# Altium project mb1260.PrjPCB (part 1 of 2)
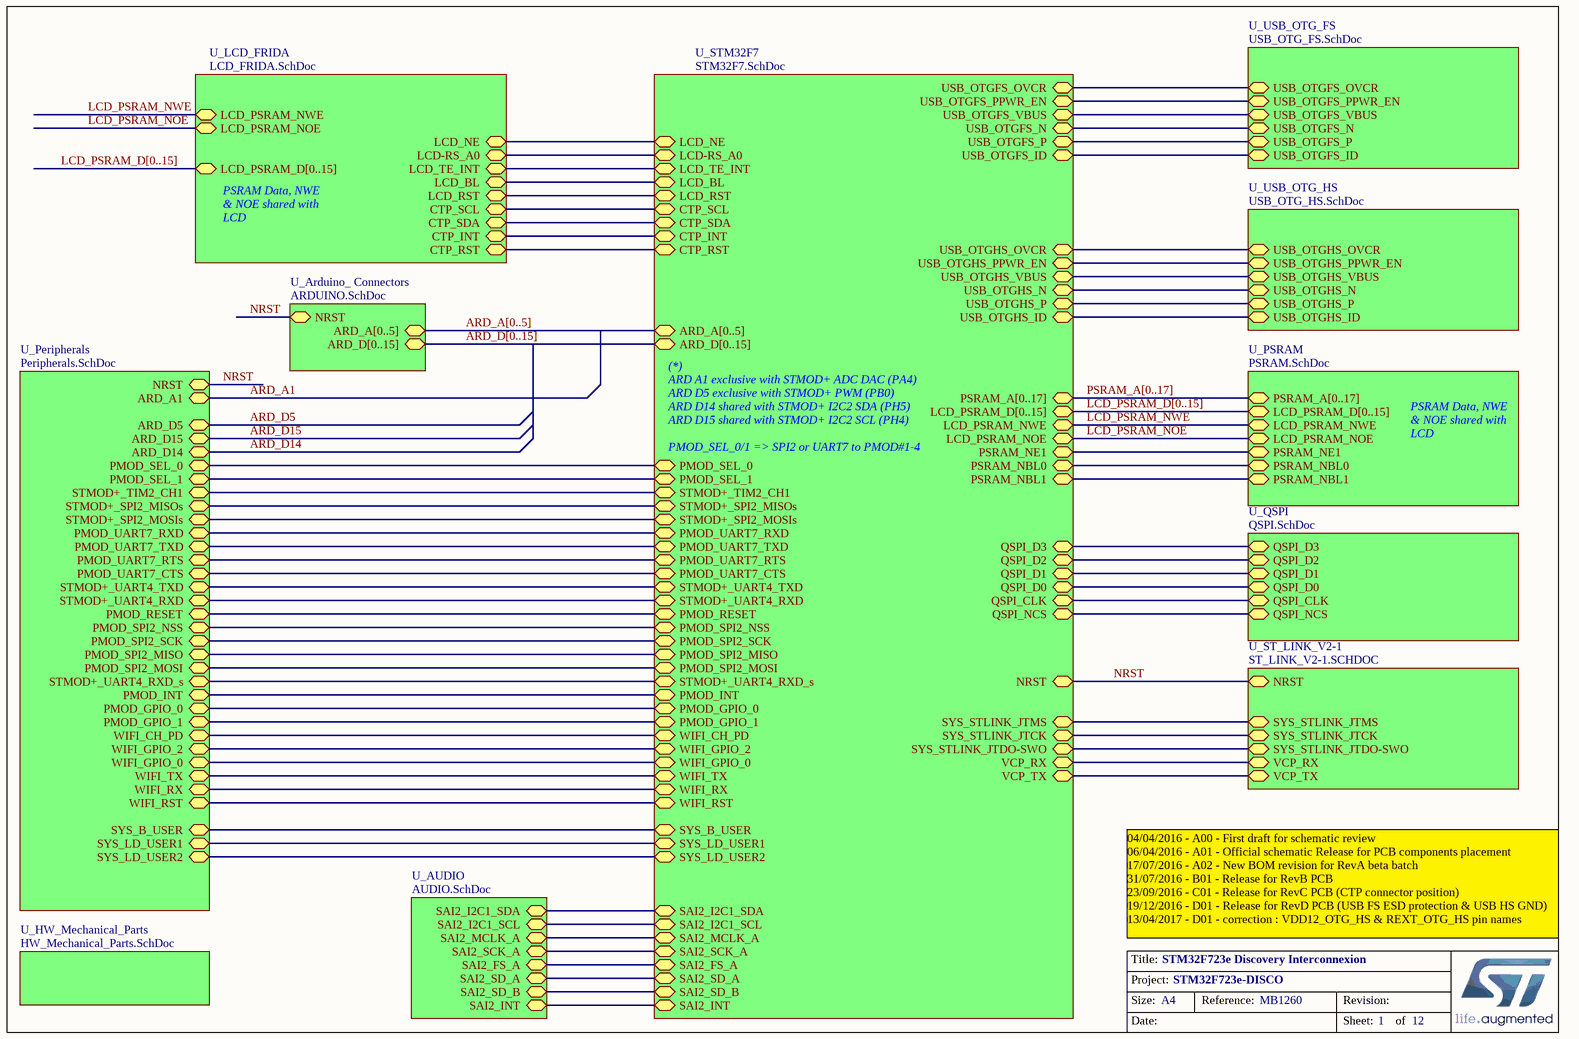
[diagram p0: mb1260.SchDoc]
BOMRevision: D-01; PCBRevision: D-01
12 sheets, 321 parts. Net scope: hierarchical (ports join the sheet entries above them; power ports are global).
Sheets:
  mb1260.SchDoc
    U_ST_LINK_V2-1 = ST_LINK_V2-1.SCHDOC
    U_AUDIO = AUDIO.SchDoc
    U_Peripherals = Peripherals.SchDoc
    U_Arduino_ Connectors = ARDUINO.SchDoc
    U_PSRAM = PSRAM.SchDoc
    U_USB_OTG_FS = USB_OTG_FS.SchDoc
    U_STM32F7 = STM32F7.SchDoc
    U_LCD_FRIDA = LCD_FRIDA.SchDoc
    U_USB_OTG_HS = USB_OTG_HS.SchDoc
    U_QSPI = QSPI.SchDoc
    U_HW_Mechanical_Parts = HW_Mechanical_Parts.SchDoc

## Sheet mb1260.SchDoc: STM32F723e Discovery Interconnexion
size A4; Author: N.P; CompanyName: STMicroelectronics; Organization: MCD/APPLIS/LMS; DocumentNumber: MB1260; Revision: D-01; SheetNumber: 1; SheetTotal: 12; Project: STM32F723e-DISCO; BOM Version: D-01

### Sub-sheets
U_Arduino_ Connectors = ARDUINO.SchDoc: NRST, ARD_D[0..15], ARD_A[0..5]
U_AUDIO = AUDIO.SchDoc: SAI2_I2C1_SDA, SAI2_I2C1_SCL, SAI2_MCLK_A, SAI2_SCK_A, SAI2_FS_A, SAI2_SD_A, SAI2_SD_B, SAI2_INT
U_HW_Mechanical_Parts = HW_Mechanical_Parts.SchDoc: no entries
U_LCD_FRIDA = LCD_FRIDA.SchDoc: LCD_NE, LCD_TE_INT, LCD_BL, LCD_RST, CTP_SCL, CTP_SDA, CTP_INT, CTP_RST, LCD_PSRAM_D[0..15], LCD_PSRAM_NWE, LCD_PSRAM_NOE, LCD-RS_A0
U_Peripherals = Peripherals.SchDoc: NRST, WIFI_TX, WIFI_RX, WIFI_RST, STMOD+_TIM2_CH1, STMOD+_SPI2_MOSIs, PMOD_UART7_RXD, PMOD_UART7_TXD, PMOD_UART7_CTS, PMOD_UART7_RTS, STMOD+_UART4_TXD, STMOD+_UART4_RXD, PMOD_RESET, PMOD_SPI2_SCK, PMOD_SPI2_NSS, PMOD_SPI2_MISO, PMOD_SPI2_MOSI, STMOD+_UART4_RXD_s, PMOD_INT, SYS_B_USER, SYS_LD_USER1, SYS_LD_USER2, ARD_D15, ARD_D14, ARD_A1, ARD_D5, PMOD_GPIO_1, PMOD_GPIO_0, WIFI_GPIO_0, WIFI_GPIO_2, WIFI_CH_PD, PMOD_SEL_1, STMOD+_SPI2_MISOs, PMOD_SEL_0
U_PSRAM = PSRAM.SchDoc: PSRAM_A[0..17], LCD_PSRAM_D[0..15], LCD_PSRAM_NWE, PSRAM_NE1, PSRAM_NBL0, PSRAM_NBL1, LCD_PSRAM_NOE
U_QSPI = QSPI.SchDoc: QSPI_D0, QSPI_D3, QSPI_D1, QSPI_CLK, QSPI_NCS, QSPI_D2
U_ST_LINK_V2-1 = ST_LINK_V2-1.SCHDOC: SYS_STLINK_JTMS, SYS_STLINK_JTCK, SYS_STLINK_JTDO-SWO, VCP_RX, VCP_TX, NRST
U_STM32F7 = STM32F7.SchDoc: QSPI_D0, QSPI_D3, QSPI_D1, QSPI_CLK, QSPI_NCS, SAI2_I2C1_SDA, SAI2_I2C1_SCL, SAI2_MCLK_A, CTP_SCL, CTP_SDA, PSRAM_A[0..17], LCD_PSRAM_D[0..15], LCD_PSRAM_NWE, PSRAM_NE1, PSRAM_NBL0, PSRAM_NBL1, QSPI_D2, ARD_D[0..15], SAI2_SCK_A, SAI2_FS_A, SAI2_SD_A, SAI2_SD_B, SAI2_INT, LCD_NE, LCD_TE_INT, LCD_BL, LCD_RST, CTP_INT, CTP_RST, WIFI_RST, WIFI_RX, WIFI_TX, ARD_A[0..5], LCD_PSRAM_NOE, SYS_STLINK_JTMS, SYS_STLINK_JTCK, SYS_STLINK_JTDO-SWO, VCP_RX, VCP_TX, USB_OTGHS_OVCR, USB_OTGHS_PPWR_EN, USB_OTGHS_VBUS, USB_OTGHS_N, USB_OTGHS_ID, USB_OTGHS_P, USB_OTGFS_OVCR, USB_OTGFS_PPWR_EN, USB_OTGFS_VBUS, USB_OTGFS_P, USB_OTGFS_N, USB_OTGFS_ID, STMOD+_TIM2_CH1, STMOD+_SPI2_MOSIs, PMOD_UART7_RXD, PMOD_UART7_TXD, PMOD_UART7_CTS, PMOD_UART7_RTS, STMOD+_UART4_TXD, STMOD+_UART4_RXD, PMOD_RESET, PMOD_SPI2_SCK, PMOD_SPI2_NSS, PMOD_SPI2_MISO, PMOD_SPI2_MOSI, STMOD+_UART4_RXD_s, PMOD_INT, NRST, SYS_B_USER, SYS_LD_USER1, SYS_LD_USER2, PMOD_GPIO_0, PMOD_GPIO_1, WIFI_GPIO_0, WIFI_GPIO_2, WIFI_CH_PD, LCD-RS_A0, PMOD_SEL_1, STMOD+_SPI2_MISOs, PMOD_SEL_0
U_USB_OTG_FS = USB_OTG_FS.SchDoc: USB_OTGFS_OVCR, USB_OTGFS_PPWR_EN, USB_OTGFS_VBUS, USB_OTGFS_P, USB_OTGFS_N, USB_OTGFS_ID
U_USB_OTG_HS = USB_OTG_HS.SchDoc: USB_OTGHS_OVCR, USB_OTGHS_PPWR_EN, USB_OTGHS_VBUS, USB_OTGHS_N, USB_OTGHS_ID, USB_OTGHS_P

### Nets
CTP_INT: sheet U_STM32F7/CTP_INT, sheet U_LCD_FRIDA/CTP_INT
CTP_RST: sheet U_STM32F7/CTP_RST, sheet U_LCD_FRIDA/CTP_RST
CTP_SCL: sheet U_STM32F7/CTP_SCL, sheet U_LCD_FRIDA/CTP_SCL
CTP_SDA: sheet U_STM32F7/CTP_SDA, sheet U_LCD_FRIDA/CTP_SDA
LCD-RS_A0: sheet U_STM32F7/LCD-RS_A0, sheet U_LCD_FRIDA/LCD-RS_A0
LCD_BL: sheet U_STM32F7/LCD_BL, sheet U_LCD_FRIDA/LCD_BL
LCD_NE: sheet U_STM32F7/LCD_NE, sheet U_LCD_FRIDA/LCD_NE
LCD_PSRAM_NOE: sheet U_PSRAM/LCD_PSRAM_NOE, sheet U_STM32F7/LCD_PSRAM_NOE, sheet U_LCD_FRIDA/LCD_PSRAM_NOE
LCD_PSRAM_NWE: sheet U_PSRAM/LCD_PSRAM_NWE, sheet U_STM32F7/LCD_PSRAM_NWE, sheet U_LCD_FRIDA/LCD_PSRAM_NWE
LCD_RST: sheet U_STM32F7/LCD_RST, sheet U_LCD_FRIDA/LCD_RST
LCD_TE_INT: sheet U_STM32F7/LCD_TE_INT, sheet U_LCD_FRIDA/LCD_TE_INT
NRST: sheet U_ST_LINK_V2-1/NRST, sheet U_Peripherals/NRST, sheet U_Arduino_ Connectors/NRST, sheet U_STM32F7/NRST
PMOD_GPIO_0: sheet U_Peripherals/PMOD_GPIO_0, sheet U_STM32F7/PMOD_GPIO_0
PMOD_GPIO_1: sheet U_Peripherals/PMOD_GPIO_1, sheet U_STM32F7/PMOD_GPIO_1
PMOD_INT: sheet U_Peripherals/PMOD_INT, sheet U_STM32F7/PMOD_INT
PMOD_RESET: sheet U_Peripherals/PMOD_RESET, sheet U_STM32F7/PMOD_RESET
PMOD_SEL_0: sheet U_Peripherals/PMOD_SEL_0, sheet U_STM32F7/PMOD_SEL_0
PMOD_SEL_1: sheet U_Peripherals/PMOD_SEL_1, sheet U_STM32F7/PMOD_SEL_1
PMOD_SPI2_MISO: sheet U_Peripherals/PMOD_SPI2_MISO, sheet U_STM32F7/PMOD_SPI2_MISO
PMOD_SPI2_MOSI: sheet U_Peripherals/PMOD_SPI2_MOSI, sheet U_STM32F7/PMOD_SPI2_MOSI
PMOD_SPI2_NSS: sheet U_Peripherals/PMOD_SPI2_NSS, sheet U_STM32F7/PMOD_SPI2_NSS
PMOD_SPI2_SCK: sheet U_Peripherals/PMOD_SPI2_SCK, sheet U_STM32F7/PMOD_SPI2_SCK
PMOD_UART7_CTS: sheet U_Peripherals/PMOD_UART7_CTS, sheet U_STM32F7/PMOD_UART7_CTS
PMOD_UART7_RTS: sheet U_Peripherals/PMOD_UART7_RTS, sheet U_STM32F7/PMOD_UART7_RTS
PMOD_UART7_RXD: sheet U_Peripherals/PMOD_UART7_RXD, sheet U_STM32F7/PMOD_UART7_RXD
PMOD_UART7_TXD: sheet U_Peripherals/PMOD_UART7_TXD, sheet U_STM32F7/PMOD_UART7_TXD
PSRAM_NBL0: sheet U_PSRAM/PSRAM_NBL0, sheet U_STM32F7/PSRAM_NBL0
PSRAM_NBL1: sheet U_PSRAM/PSRAM_NBL1, sheet U_STM32F7/PSRAM_NBL1
PSRAM_NE1: sheet U_PSRAM/PSRAM_NE1, sheet U_STM32F7/PSRAM_NE1
QSPI_CLK: sheet U_STM32F7/QSPI_CLK, sheet U_QSPI/QSPI_CLK
QSPI_D0: sheet U_STM32F7/QSPI_D0, sheet U_QSPI/QSPI_D0
QSPI_D1: sheet U_STM32F7/QSPI_D1, sheet U_QSPI/QSPI_D1
QSPI_D2: sheet U_STM32F7/QSPI_D2, sheet U_QSPI/QSPI_D2
QSPI_D3: sheet U_STM32F7/QSPI_D3, sheet U_QSPI/QSPI_D3
QSPI_NCS: sheet U_STM32F7/QSPI_NCS, sheet U_QSPI/QSPI_NCS
SAI2_FS_A: sheet U_AUDIO/SAI2_FS_A, sheet U_STM32F7/SAI2_FS_A
SAI2_I2C1_SCL: sheet U_AUDIO/SAI2_I2C1_SCL, sheet U_STM32F7/SAI2_I2C1_SCL
SAI2_I2C1_SDA: sheet U_AUDIO/SAI2_I2C1_SDA, sheet U_STM32F7/SAI2_I2C1_SDA
SAI2_INT: sheet U_AUDIO/SAI2_INT, sheet U_STM32F7/SAI2_INT
SAI2_MCLK_A: sheet U_AUDIO/SAI2_MCLK_A, sheet U_STM32F7/SAI2_MCLK_A
SAI2_SCK_A: sheet U_AUDIO/SAI2_SCK_A, sheet U_STM32F7/SAI2_SCK_A
SAI2_SD_A: sheet U_AUDIO/SAI2_SD_A, sheet U_STM32F7/SAI2_SD_A
SAI2_SD_B: sheet U_AUDIO/SAI2_SD_B, sheet U_STM32F7/SAI2_SD_B
STMOD+_SPI2_MISOs: sheet U_Peripherals/STMOD+_SPI2_MISOs, sheet U_STM32F7/STMOD+_SPI2_MISOs
STMOD+_SPI2_MOSIs: sheet U_Peripherals/STMOD+_SPI2_MOSIs, sheet U_STM32F7/STMOD+_SPI2_MOSIs
STMOD+_TIM2_CH1: sheet U_Peripherals/STMOD+_TIM2_CH1, sheet U_STM32F7/STMOD+_TIM2_CH1
STMOD+_UART4_RXD: sheet U_Peripherals/STMOD+_UART4_RXD, sheet U_STM32F7/STMOD+_UART4_RXD
STMOD+_UART4_RXD_s: sheet U_Peripherals/STMOD+_UART4_RXD_s, sheet U_STM32F7/STMOD+_UART4_RXD_s
STMOD+_UART4_TXD: sheet U_Peripherals/STMOD+_UART4_TXD, sheet U_STM32F7/STMOD+_UART4_TXD
SYS_B_USER: sheet U_Peripherals/SYS_B_USER, sheet U_STM32F7/SYS_B_USER
SYS_LD_USER1: sheet U_Peripherals/SYS_LD_USER1, sheet U_STM32F7/SYS_LD_USER1
SYS_LD_USER2: sheet U_Peripherals/SYS_LD_USER2, sheet U_STM32F7/SYS_LD_USER2
SYS_STLINK_JTCK: sheet U_ST_LINK_V2-1/SYS_STLINK_JTCK, sheet U_STM32F7/SYS_STLINK_JTCK
SYS_STLINK_JTDO-SWO: sheet U_ST_LINK_V2-1/SYS_STLINK_JTDO-SWO, sheet U_STM32F7/SYS_STLINK_JTDO-SWO
SYS_STLINK_JTMS: sheet U_ST_LINK_V2-1/SYS_STLINK_JTMS, sheet U_STM32F7/SYS_STLINK_JTMS
USB_OTGFS_ID: sheet U_USB_OTG_FS/USB_OTGFS_ID, sheet U_STM32F7/USB_OTGFS_ID
USB_OTGFS_N: sheet U_USB_OTG_FS/USB_OTGFS_N, sheet U_STM32F7/USB_OTGFS_N
USB_OTGFS_OVCR: sheet U_USB_OTG_FS/USB_OTGFS_OVCR, sheet U_STM32F7/USB_OTGFS_OVCR
USB_OTGFS_P: sheet U_USB_OTG_FS/USB_OTGFS_P, sheet U_STM32F7/USB_OTGFS_P
USB_OTGFS_PPWR_EN: sheet U_USB_OTG_FS/USB_OTGFS_PPWR_EN, sheet U_STM32F7/USB_OTGFS_PPWR_EN
USB_OTGFS_VBUS: sheet U_USB_OTG_FS/USB_OTGFS_VBUS, sheet U_STM32F7/USB_OTGFS_VBUS
USB_OTGHS_ID: sheet U_STM32F7/USB_OTGHS_ID, sheet U_USB_OTG_HS/USB_OTGHS_ID
USB_OTGHS_N: sheet U_STM32F7/USB_OTGHS_N, sheet U_USB_OTG_HS/USB_OTGHS_N
USB_OTGHS_OVCR: sheet U_STM32F7/USB_OTGHS_OVCR, sheet U_USB_OTG_HS/USB_OTGHS_OVCR
USB_OTGHS_P: sheet U_STM32F7/USB_OTGHS_P, sheet U_USB_OTG_HS/USB_OTGHS_P
USB_OTGHS_PPWR_EN: sheet U_STM32F7/USB_OTGHS_PPWR_EN, sheet U_USB_OTG_HS/USB_OTGHS_PPWR_EN
USB_OTGHS_VBUS: sheet U_STM32F7/USB_OTGHS_VBUS, sheet U_USB_OTG_HS/USB_OTGHS_VBUS
VCP_RX: sheet U_ST_LINK_V2-1/VCP_RX, sheet U_STM32F7/VCP_RX
VCP_TX: sheet U_ST_LINK_V2-1/VCP_TX, sheet U_STM32F7/VCP_TX
WIFI_CH_PD: sheet U_Peripherals/WIFI_CH_PD, sheet U_STM32F7/WIFI_CH_PD
WIFI_GPIO_0: sheet U_Peripherals/WIFI_GPIO_0, sheet U_STM32F7/WIFI_GPIO_0
WIFI_GPIO_2: sheet U_Peripherals/WIFI_GPIO_2, sheet U_STM32F7/WIFI_GPIO_2
WIFI_RST: sheet U_Peripherals/WIFI_RST, sheet U_STM32F7/WIFI_RST
WIFI_RX: sheet U_Peripherals/WIFI_RX, sheet U_STM32F7/WIFI_RX
WIFI_TX: sheet U_Peripherals/WIFI_TX, sheet U_STM32F7/WIFI_TX

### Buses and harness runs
bus ARD_A[0..5] = sheet U_Arduino_ Connectors/ARD_A[0..5] = sheet U_STM32F7/ARD_A[0..5]
bus ARD_D[0..15] = sheet U_Arduino_ Connectors/ARD_D[0..15] = sheet U_STM32F7/ARD_D[0..15]
bus LCD_PSRAM_D[0..15] = sheet U_LCD_FRIDA/LCD_PSRAM_D[0..15]
bus LCD_PSRAM_D[0..15] = sheet U_PSRAM/LCD_PSRAM_D[0..15] = sheet U_STM32F7/LCD_PSRAM_D[0..15]
bus PSRAM_A[0..17] = sheet U_PSRAM/PSRAM_A[0..17] = sheet U_STM32F7/PSRAM_A[0..17]

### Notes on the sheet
- PSRAM Data, NWE & NOE shared with LCD
- (*)
  ARD A1 exclusive with STMOD+ ADC DAC (PA4)
  ARD D5 exclusive with STMOD+ PWM (PB0)
  ARD D14 shared with STMOD+ I2C2 SDA (PH5)
  ARD D15 shared with STMOD+ I2C2 SCL (PH4)
- PMOD_SEL_0/1 => SPI2 or UART7 to PMOD#1-4
- 04/04/2016 - A00 - First draft for schematic review
  06/04/2016 - A01 - Official schematic Release for PCB components placement
  17/07/2016 - A02 - New BOM revision for RevA beta batch
  31/07/2016 - B01 - Release for RevB PCB
  23/09/2016 - C01 - Release for RevC PCB (CTP connector position)
  19/12/2016 - D01 - Release for RevD PCB (USB FS ESD protection & USB HS GND)
  13/04/2017 - D01 - correction : VDD12_OTG_HS & REXT_OTG_HS pin names

## Sheet ST_LINK_V2-1.SCHDOC: ST-LINK/V2-1 with support of SWD only
size A4; Author: N.P; CompanyName: STMicroelectronics; Organization: MCD/APPLIS/LMS; DocumentNumber: MB1260; Revision: D-01; SheetNumber: 2; SheetTotal: 12; Project: STM32F723e-DISCO; BOM Version: D-01
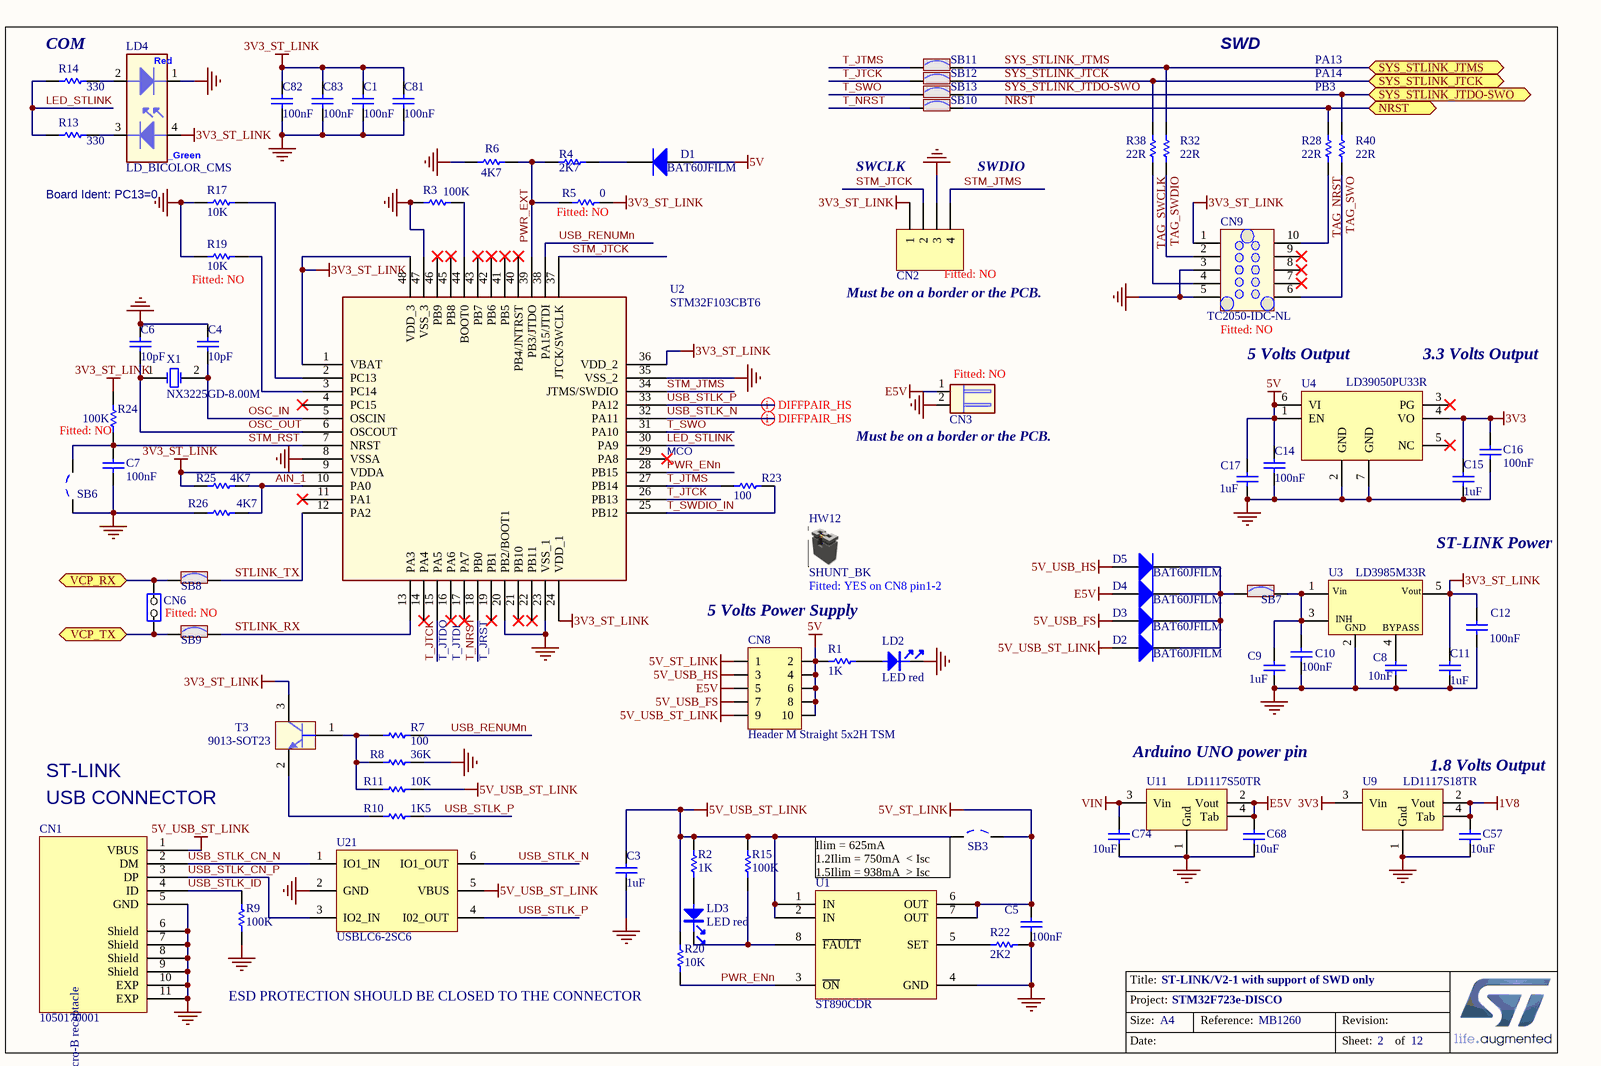
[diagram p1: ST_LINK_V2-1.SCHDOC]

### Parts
C1  100nF  [0402C]
C3  1uF  [0603C]
C4  10pF  [0402C]
C5  100nF  [0402C]
C6  10pF  [0402C]
C7  100nF  [0402C]
C8  value 10nF  [0603C]  (hidden comment: 10nF_X7R_10%_0603)
C9  1uF  [0603C]
C10  100nF  [0402C]
C11  1uF  [0603C]
C12  100nF  [0402C]
C14  100nF  [0402C]
C15  1uF  [0603C]
C16  100nF  [0402C]
C17  1uF  [0603C]
C57  10uF  [0603C]
C68  10uF  [0805C]
C74  10uF  [0805C]
C81  100nF  [0402C]
C82  100nF  [0402C]
C83  100nF  [0402C]
CN1  1050170001  [MICRO_USB_B_105017]
CN2  Fitted: NO  [HDR_1X4_2R54]  (hidden comment: Header 4)
CN3  Fitted: NO  [HDR_1X2_2R54_RA_11R35]  (hidden comment: WF25402-06421)
CN6  Fitted: NO  [SIP2]  (hidden comment: JP2)
CN8  Header M Straight 5x2H TSM  [TSM-105-01-S-DV]
CN9  TC2050-IDC-NL  Fitted: NO  [TC2050-IDC-NL]
D1  BAT60JFILM  [SOD-323]
D2  BAT60JFILM  [SOD-323]
D3  BAT60JFILM  [SOD-323]
D4  BAT60JFILM  [SOD-323]
D5  BAT60JFILM  [SOD-323]
HW12  SHUNT_BK  Fitted: YES on CN8 pin1-2  (mechanical)
LD2  LED red  [0603D]
LD3  LED red  [0603D]
LD4  LD_BICOLOR_CMS  [LED2_3528]
R1  1K  [0402R]
R2  1K  [0402R]
R3  value 100K  [0402R]  (hidden comment: 100K_1%_0402)
R4  2K7  [0402R]
R5  Fitted: NO  [0402R]  (hidden comment: 0)
R6  value 4K7  [0402R]  (hidden comment: 4K7_1%_0402)
R7  100  [0402R]
R8  36K  [0402R]
R9  value 100K  [0402R]  (hidden comment: 100K_1%_0402)
R10  1K5  [0402R]
R11  10K  [0402R]
R13  330  [0402R]
R14  330  [0402R]
R15  value 100K  [0402R]  (hidden comment: 100K_1%_0402)
R17  10K  [0402R]
R19  10K  Fitted: NO  [0402R]
R20  10K  [0402R]
R22  2K2  [0402R]
R23  100  [0402R]
R24  value 100K  Fitted: NO  [0402R]  (hidden comment: 100K_1%_0402)
R25  value 4K7  [0402R]  (hidden comment: 4K7_1%_0402)
R26  value 4K7  [0402R]  (hidden comment: 4K7_1%_0402)
R28  22R  [R0603]
R32  22R  [R0603]
R38  22R  [R0603]
R40  22R  [R0603]
SB3  Solder Bridge OFF  [JP2_SMD]  (value not drawn)
SB6  Solder Bridge OFF  [JP2_SMD]  (value not drawn)
SB7  Solder Bridge ON  [JP2_SMD]  (value not drawn)
SB8  Solder Bridge ON  [JP2_SMD]  (value not drawn)
SB9  Solder Bridge ON  [JP2_SMD]  (value not drawn)
SB10  Solder Bridge ON  [JP2_SMD]  (value not drawn)
SB11  Solder Bridge ON  [JP2_SMD]  (value not drawn)
SB12  Solder Bridge ON  [JP2_SMD]  (value not drawn)
SB13  Solder Bridge ON  [JP2_SMD]  (value not drawn)
T3  9013-SOT23  [SOT-23]
U1  ST890CDR  [SOIC8_1R27_4R9X6]
U2  STM32F103CBT6  [LQFP48_0R5_9X9]
U3  LD3985M33R  [SOT-23-5L]
U4  LD39050PU33R  [DFN6_0R95_3X3]
U9  LD1117S18TR  [SOT-223]
U11  LD1117S50TR  [SOT-223]
U21  USBLC6-2SC6  [SOT23-6]
X1  NX3225GD-8.00M  [XTAL_2SM_3R2X2R5_H1]

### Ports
NRST, SYS_STLINK_JTCK, SYS_STLINK_JTDO-SWO, SYS_STLINK_JTMS, VCP_RX, VCP_TX

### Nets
1V8: C57.2 U9.2(Vout) U9.4(Tab)
3V3: C15.2 C16.2 U4.4(VO) U9.3(Vin)
3V3_ST_LINK: C1.1 C11.2 C12.2 C81.2 C82.2 C83.2 CN2.1 CN9.1 LD4.4 R5.2 R24.2 R25.1 T3.3(C) U2.1(VBAT) U2.9(VDDA) U2.24(VDD_1) U2.36(VDD_2) U2.48(VDD_3) U3.5(Vout)
5V: C14.2 C17.2 CN8.2 CN8.4 CN8.6 CN8.8 CN8.10 D1.1(A) R1.1 U4.1(EN) U4.6(VI)
5V_ST_LINK: C5.2 CN8.1 SB3.2 U1.6(OUT) U1.7(OUT)
5V_USB_FS: CN8.7 D3.1(A)
5V_USB_HS: CN8.3 D5.1(A)
5V_USB_ST_LINK: C3.2 CN1.1(VBUS) CN8.9 D2.1(A) R2.2 R11.1 R15.2 R20.2 SB3.1 U1.1(IN) U1.2(IN) U21.5(VBUS)
E5V: C68.2 CN3.1 CN8.5 D4.1(A) U11.2(Vout) U11.4(Tab)
GND: C1.2 C3.1 C4.1 C5.1 C6.1 C7.1 C8.1 C9.1 C10.1 C11.1 C12.1 C14.1 C15.1 C16.1 C17.1 C57.1 C68.1 C74.1 C81.1 C82.1 C83.1 CN1.5(GND) CN1.6(Shield) CN1.7(Shield) CN1.8(Shield) CN1.9(Shield) CN1.10(EXP) CN1.11(EXP) CN2.3 CN3.2 CN9.3 CN9.5 LD2.2 LD4.1 R3.1 R6.1 R8.1 R9.1 R17.1 R19.1 R22.2 R26.1 SB6.1 U1.4(GND) U2.8(VSSA) U2.20(PB2/BOOT1) U2.23(VSS_1) U2.35(VSS_2) U2.47(VSS_3) U3.2(GND) U4.2(GND) U4.7(GND) U9.1(Gnd) U11.1(Gnd) U21.2(GND)
VIN: C74.2 U11.3(Vin)
AIN_1: R25.2 R26.2 U2.10(PA0)
LED_STLINK: R13.1 R14.1 U2.30(PA9)
NRST: R28.2 SB10.2 ; port NRST
OSC_IN: C4.2 U2.5(OSCIN) X1.2(OSC2)
OSC_OUT: C6.2 U2.6(OSCOUT) X1.1(OSC1)
PWR_ENn: R20.1 U1.3(~{ON}) U2.28(PB15)
PWR_EXT: R4.1 R5.1 R6.2 U2.39(PB3/JTDO)
STLINK_RX: SB9.2 U2.13(PA3)
STLINK_TX: SB8.2 U2.12(PA2)
STM_JTCK: CN2.2 U2.37(JTCK/SWCLK)
STM_JTMS: CN2.4 U2.34(JTMS/SWDIO)
STM_RST: C7.2 R24.1 SB6.2 U2.7(NRST)
SYS_STLINK_JTCK: R38.2 SB12.2 ; port SYS_STLINK_JTCK
SYS_STLINK_JTDO-SWO: R40.2 SB13.2 ; port SYS_STLINK_JTDO-SWO
SYS_STLINK_JTMS: R32.2 SB11.2 ; port SYS_STLINK_JTMS
T_JTCK: SB12.1 U2.15(PA5) U2.26(PB13)
T_JTMS: R23.1 SB11.1 U2.27(PB14)
T_NRST: SB10.1 U2.18(PB0)
T_SWDIO_IN: R23.2 U2.25(PB12)
T_SWO: SB13.1 U2.31(PA10)
TAG_NRST: CN9.10 R28.1
TAG_SWCLK: CN9.4 R38.1
TAG_SWDIO: CN9.2 R32.1
TAG_SWO: CN9.6 R40.1
USB_RENUMn: R7.2 U2.38(PA15/JTDI)
USB_STLK_CN_N: CN1.2(DM) U21.1(IO1_IN)
USB_STLK_CN_P: CN1.3(DP) U21.3(IO2_IN)
USB_STLK_ID: CN1.4(ID) R9.2
USB_STLK_N: U2.32(PA11) U21.6(IO1_OUT)
USB_STLK_P: R10.2 U2.33(PA12) U21.4(I02_OUT)
VCP_RX: CN6.2(NO) SB8.1 ; port VCP_RX
VCP_TX: CN6.1(COMMON) SB9.1 ; port VCP_TX
NetC8_2: C8.2 U3.4(BYPASS)
NetC9_2: C9.2 C10.2 SB7.2 U3.1(Vin) U3.3(CE)
NetD1_2: D1.2(K) R4.2
NetD2_2: D2.2(K) D3.2(K) D4.2(K) D5.2(K) SB7.1
NetLD2_1: LD2.1 R1.2
NetLD3_1: LD3.1 R2.1
NetLD3_2: LD3.2 R15.1 U1.8(~{FAULT})
NetLD4_2: LD4.2 R14.2
NetLD4_3: LD4.3 R13.2
NetR3_2: R3.2 U2.44(BOOT0)
NetR7_1: R7.1 R8.2 R11.2 T3.1(B)
NetR10_1: R10.1 T3.2(E)
NetR17_2: R17.2 U2.2(PC13)
NetR19_2: R19.2 U2.3(PC14)
NetR22_1: R22.1 U1.5(SET)

Not connected (* = marked no-connect by the designer): CN9 7* 8* 9*; U2 4(PC15)* 11(PA1)* 14(PA4)* 16(PA6)* 17(PA7)* 19(PB1)* 21(PB10)* 22(PB11)* 29(PA8)* 40(PB4/JNTRST)* 41(PB5)* 42(PB6)* 43(PB7)* 45(PB8)* 46(PB9)*; U4 3(PG)* 5(NC)*

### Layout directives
differential pair: USB_STLK_N, USB_STLK_P

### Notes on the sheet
- (near R14) COM
- SWD
- PA13
- PB3
- PA14
- Board Ident: PC13=0
- SWCLK
- SWDIO
- Must be on a border or the PCB.
- 5 Volts Output
- (near U4) 3.3 Volts Output
- MCO
- (near CN3) Must be on a border or the PCB.
- ST-LINK Power
- (near U2) T_JTDO
- (near U2) T_JTDI
- (near U2) T_JRST
- 5 Volts Power Supply
- ST-LINK
- (near CN1) USB CONNECTOR
- (near U11) Arduino UNO power pin
- (near U9) 1.8 Volts Output
- (near SB3) Ilim = 625mA
  1.2Ilim = 750mA  < Isc
  1.5Ilim = 938mA  > Isc
- ESD PROTECTION SHOULD BE CLOSED TO THE CONNECTOR

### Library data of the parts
C1 C5 C7 C10 C12 C14 C16 C81-C83 = Cap_100nF_X7R_10%_0402: Capacitor,100nF,16V,X7R,10%,0402,YAGEO; Manuf_Part_1: CC0402KRX7R7BB104; Ordered by: Subcon; Fitted: YES
C3 C9 C11 C15 C17 = Cap_1uF_X5R_10%_0603: Capacitor,1uF,16V,X5R,10%,0603,YAGEO; Manuf_Part_1: CC0603KRX5R7BB105; Ordered by: Subcon; Fitted: YES
C4 C6 = Cap_10pF_NPO_5%_0402: Capacitor,10pF,50V,NPO,5%,0402,YAGEO; Order: CC0402JRNPO9BN100; Ordered by: Subcon; Fitted: YES
C8 = Cap_10nF_X7R_10%_0603: Capacitor,10nF,50V,X7R,10%,0603,YAGEO; Manuf_Part_1: CC0603KRX7R9BB103; Ordered by: Subcon; Fitted: YES
C57 = Cap_10uF_X5R_10%_0603: Capacitor,10uF,6.3V,X5R,10%,0603,YAGEO; Manuf_Part_1: CC0603KRX5R5BB106; Ordered by: Subcon; Fitted: YES
C68 C74 = Cap_10uF_X5R_10%_0805: Capacitor,10uF,25V,X5R,10%,0805,YAGEO; Manuf_Part_1: CC0805KRX5R8BB106; Ordered by: Subcon; Fitted: YES
CN1 = 1050170001: USB-MICRO-B, 1050170001, SMT, MOLEX; Ordered by: Subcon; Fitted: YES
CN2 = Header 4: Header, 4-Pin; Ordered by: Subcon
CN3 = JP2_RA: Header, 2-Pins, Single row, Right Angle, 2.54 mm pitch, DIP; Manuf_1: ATOM; Ordered by: Subcon
CN6 = JP2: Ordered by: Subcon
CN8 = Header 5X2M TSM: Header Male TSM, 5-Pin, Dual row, Straight, AMD; Manuf_Part_1: TSM-105-01-L-DV; Manuf_1: SAMTEC; Fitted: YES; Ordered by: Subcon
CN9 = Tag-10-C: Tag_Connector Header, 10-Pin, Dual row No legs; Manuf_Part_1: TC2050-IDC-NL-FP; Ordered_By: Subcon
D1-D5 = BAT60JFILM: Manuf_1: STM; Provided: ST; ECCN_US/EU: EAR99/NEC; Ref St: 9151097; Fitted: YES
HW12 = Shunt 2.54mm: SHUNT 2.54mm BLACK; Manuf_1: SAMTEC; Manuf_Part_1: SNT-100-BK-G; Ordered_By: Subcon
LD2 LD3 = LED_red: LED red 0603; Manuf_1: everlight; Manuf_Part_1: 19-213-R6C-AP1Q2B/3T; Ordered by: Subcon; Fitted: YES
LD4 = LD_BICOLOR_CMS: Bicolor Led; Manuf_Part_1: HSMF-A201-A00J1; Manuf_1: Avago Technologies; Manuf_2: everluck; Manuf_Part_2: LE-RGW35280; Ref St: xxxxxx; Ordered by: Subcon; Fitted: YES
R1 R2 = Res_1K_1%_0402: Resistor,1K,0402,1%,YAGEO; Manuf_Part_1: RC0402FR-071KL; Ordered by: Subcon; Fitted: YES
R3 R9 R15 = Res_100K_1%_0402: Resistor,100K,0402,1%,YAGEO; Manuf_Part_1: RC0402FR-07100KL; Manuf_Part_2: RT0402FRE07100KL; Ordered by: Subcon; Fitted: YES
R4 = Res_2K7_1%_0402: Resistor,2K7,0402,1%,YAGEO; Manuf_Part_1: RC0402FR-072K7L; Ordered by: Subcon; Fitted: YES
R5 = Res_0_5%_0402: Resistor,0,0402,5%,YAGEO; Manuf_Part_1: RC0402JR-070RL; Order: 2363467; Ordered by: Subcon
R6 R25 R26 = Res_4K7_1%_0402: Resistor,4K7,0402,1%,YAGEO; Manuf_Part_1: RC0402FR-074K7L; Manuf_Part_2: RT0402FRE074K7L; Ordered by: Subcon; Fitted: YES
R7 R23 = Res_100_1%_0402: Resistor,100,0402,1%,YAGEO; Manuf_Part_1: RC0402FR-07100RL; Order: 9239111; Ordered by: Subcon; Fitted: YES
R8 = Res_36K_1%_0402: Resistor,36K,0402,1%,YAGEO; Manuf_Part_1: RC0402FR-0736KL; Ordered by: Subcon; Fitted: YES
R10 = Res_1K5_1%_0402: Resistor,1K5,0402,1%,YAGEO; Manuf_Part_1: RC0402FR-071K5L; Ordered by: Subcon; Fitted: YES
R11 R17 R20 = Res_10K_1%_0402: Resistor,10K,0402,1%,YAGEO; Manuf_Part_1: RC0402FR-0710KL; Ordered by: Subcon; Fitted: YES
R13 R14 = Res_330_1%_0402: Resistor,330,0402,1%,YAGEO; Manuf_Part_1: RC0402FR-07330RL; Ordered by: Subcon; Fitted: YES
R19 = Res_10K_1%_0402: Resistor,10K,0402,1%,YAGEO; Manuf_Part_1: RC0402FR-0710KL; Ordered by: Subcon
R22 = Res_2K2_1%_0402: Resistor,2K2,0402,1%,YAGEO; Manuf_Part_1: RC0402FR-072K2L; Ordered by: Subcon; Fitted: YES
R24 = Res_100K_1%_0402: Resistor,100K,0402,1%,YAGEO; Manuf_Part_1: RC0402FR-07100KL; Manuf_Part_2: RT0402FRE07100KL; Ordered by: Subcon
R28 R32 R38 R40 = Res_22_1%_0603: Resistor,22R,0603,1%,Yageo; Manuf_Part_1: RC0603FR-0722RL; Fitted: YES; Ordered_By: Subcon
SB3 SB6 = SB_OFF: Fitted: NO; Ordered by: Subcon
SB7-SB13 = SB_ON: Fitted: YES; Ordered by: Subcon
T3 = 9013-SOT23: NPN Bipolar Transistor; Manuf_1: NXP; Manuf_Part_1: BSR14; Order: 1081310; Ordered by: Subcon; Fitted: YES
U1 = ST890CDR: 1.2 A current limited high-side power switch with thermal shutdown; Manuf_1: STM; ECCN_US/EU: EAR99/NEC; Provided: ST; Fitted: YES
U2 = STM32F103CBT6: Medium-density performance line ARM-based 32-bit MCU with 128KB Flash; Manuf_1: STM; Ref St: xxxxxxxx; Provided: ST; ECCN_US/EU: 3A991A2/NEC; Fitted: YES
U3 = LD3985M33R: Ultra low drop-low noise BiCMOS voltage, regulators low ESR capacitors compatible; Manuf_1: STM; Provided: ST; Ref St: 9176161; ECCN_US/EU: EAR99/NEC; Fitted: YES
U4 = LD39050P: Ultra low drop-low , 500 mA low quiescent current; Manuf_1: STM; Provided: ST; ECCN_US/EU: EAR99/NEC; Ref St: xxxxxxxx; Fitted: YES
U9 = LD1117S18TR: LOW DROP FIXED AND ADJUSTABLE POSITIVE VOLTAGE REGULATORS (1.8 Volts); Manuf_1: STM; Ref St: 9176180; ECCN_US/EU: EAR99/NEC; Provided: ST; Fitted: YES
U11 = LD1117S50TR: IC REG LDO 5V 0.8A SOT223; Manuf_1: STM; Ordered by: ST; ECCN_US/EU: EAR99/NEC; Ref St: 9176133; Fitted: YES
U21 = USBLC6-2SC6: Very low capacitance ESD protection; Manuf_1: STM; Provided: ST; ECCN_US/EU: EAR99/NEC; Fitted: YES
X1 = XTAL_8M_NX3225GD: Crystal 8Mhz, 8pF, -+50PPM, SMD; Manuf_1: NDK; Manuf_Part_1: NX3225GD 8MHz EXS00A-CG04874; Manuf_Part_2: NX3225GD-8.000M-STD-CRA-3; ECCN_US/EU: EAR99/NEC; NDK Ref: X3127326; Ref St: 9157029; Provided: ST; Fitted: YES

## Sheet AUDIO.SchDoc: Audio Codec WOLFSON and Audio Connectors
size A4; Author: N.P; CompanyName: STMicroelectronics; Organization: MCD/APPLIS/LMS; DocumentNumber: MB1260; Revision: D-01; SheetNumber: 4; SheetTotal: 12; Project: STM32F723e-DISCO; BOM Version: D-01
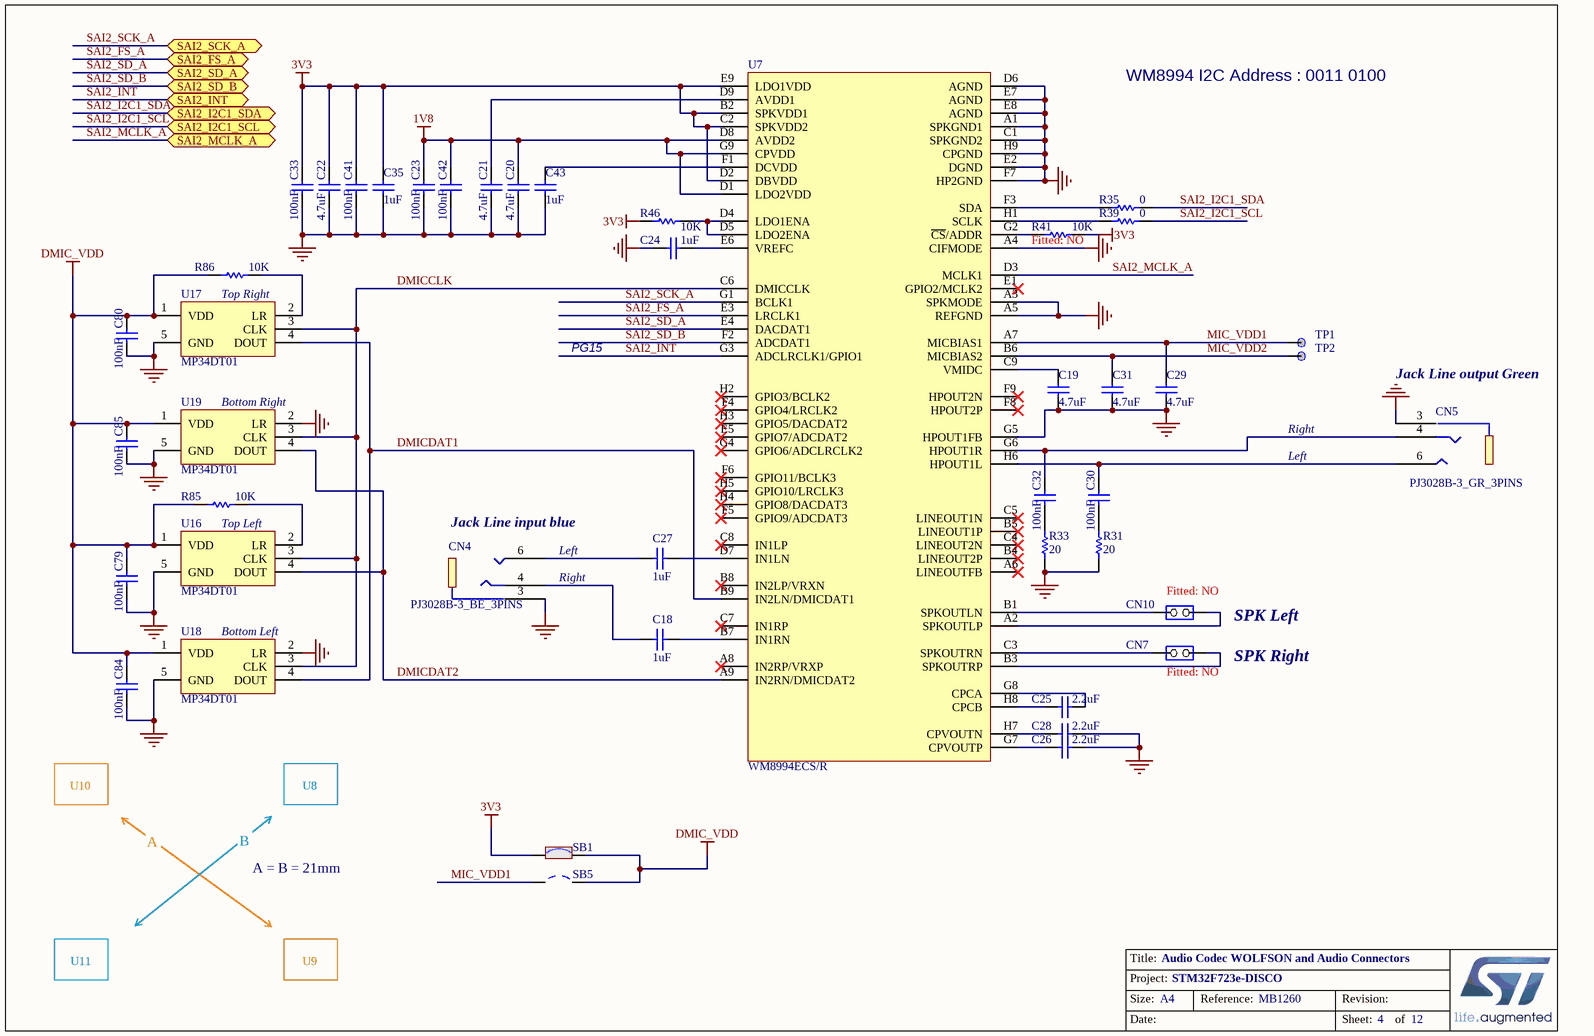
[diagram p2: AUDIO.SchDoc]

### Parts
C18  1uF  [0603C]
C19  4.7uF  [0603C]
C20  4.7uF  [0603C]
C21  4.7uF  [0603C]
C22  4.7uF  [0603C]
C23  100nF  [0402C]
C24  1uF  [0603C]
C25  value 2.2uF  [0603C]  (hidden comment: 2.2uF_X5R_10%_0603)
C26  value 2.2uF  [0603C]  (hidden comment: 2.2uF_X5R_10%_0603)
C27  1uF  [0603C]
C28  value 2.2uF  [0603C]  (hidden comment: 2.2uF_X5R_10%_0603)
C29  4.7uF  [0603C]
C30  100nF  [0402C]
C31  4.7uF  [0603C]
C32  100nF  [0402C]
C33  100nF  [0402C]
C35  1uF  [0603C]
C41  100nF  [0402C]
C42  100nF  [0402C]
C43  1uF  [0603C]
C79  100nF  [0402C]
C80  100nF  [0402C]
C84  100nF  [0402C]
C85  100nF  [0402C]
CN4  PJ3028B-3_BE_3PINS  [PJ3028B]
CN5  PJ3028B-3_GR_3PINS  [PJ3028B]
CN7  Fitted: NO  [SIP2]  (hidden comment: JP2)
CN10  Fitted: NO  [SIP2]  (hidden comment: JP2)
R31  20  [0402R]
R33  20  [0402R]
R35  0  [0402R]
R39  0  [0402R]
R41  Fitted: NO  [0402R]  (hidden comment: 10K)
R46  10K  [0402R]
R85  10K  [0402R]
R86  10K  [0402R]
SB1  Solder Bridge ON  [JP2_SMD]  (value not drawn)
SB5  Solder Bridge OFF  [JP2_SMD]  (value not drawn)
TP1  TP  [TP_C40]  (value not drawn)
TP2  TP  [TP_C40]  (value not drawn)
U7  WM8994ECS/R  [BGA72_0R5_4R5X4]
U16  MP34DT01  [MP34DT01TR]
U17  MP34DT01  [MP34DT01TR]
U18  MP34DT01  [MP34DT01TR]
U19  MP34DT01  [MP34DT01TR]

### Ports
SAI2_FS_A, SAI2_I2C1_SCL, SAI2_I2C1_SDA, SAI2_INT, SAI2_MCLK_A, SAI2_SCK_A, SAI2_SD_A, SAI2_SD_B

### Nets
1V8: C20.1 C23.1 C42.1 U7.D1(LDO2VDD) U7.D8(AVDD2) U7.G9(CPVDD)
3V3: C22.1 C33.1 C35.2 C41.1 R41.1 R46.2 SB1.1 U7.B2(SPKVDD1) U7.C2(SPKVDD2) U7.D2(DBVDD) U7.E9(LDO1VDD)
DMIC_VDD: C79.1 C80.1 C84.1 C85.1 R85.2 R86.2 SB1.2 SB5.2 U16.1(VDD) U17.1(VDD) U18.1(VDD) U19.1(VDD)
GND: C19.1 C20.2 C21.2 C22.2 C23.2 C24.2 C26.2 C28.2 C29.1 C31.1 C33.2 C35.1 C41.2 C42.2 C43.1 C79.2 C80.2 C84.2 C85.2 CN4.3 CN5.3 R31.2 R33.2 U7.A1(SPKGND1) U7.A3(SPKMODE) U7.A4(CIFMODE) U7.A5(REFGND) U7.C1(SPKGND2) U7.D6(AGND) U7.E2(DGND) U7.E7(AGND) U7.E8(AGND) U7.F7(HP2GND) U7.G5(HPOUT1FB) U7.H9(CPGND) U16.5(GND) U17.5(GND) U18.2(LR) U18.5(GND) U19.2(LR) U19.5(GND)
DMICCLK: U7.C6(DMICCLK) U16.3(CLK) U17.3(CLK) U18.3(CLK) U19.3(CLK)
DMICDAT1: U7.B9(IN2LN/DMICDAT1) U17.4(DOUT) U18.4(DOUT)
DMICDAT2: U7.A9(IN2RN/DMICDAT2) U16.4(DOUT) U19.4(DOUT)
MIC_VDD1: C29.2 SB5.1 TP1.1 U7.A7(MICBIAS1)
MIC_VDD2: C31.2 TP2.1 U7.B6(MICBIAS2)
SAI2_FS_A: U7.E3(LRCLK1) ; port SAI2_FS_A
SAI2_I2C1_SCL: R39.1 ; port SAI2_I2C1_SCL
SAI2_I2C1_SDA: R35.1 ; port SAI2_I2C1_SDA
SAI2_INT: U7.G3(ADCLRCLK1/GPIO1) ; port SAI2_INT
SAI2_MCLK_A: U7.D3(MCLK1) ; port SAI2_MCLK_A
SAI2_SCK_A: U7.G1(BCLK1) ; port SAI2_SCK_A
SAI2_SD_A: U7.E4(DACDAT1) ; port SAI2_SD_A
SAI2_SD_B: U7.F2(ADCDAT1) ; port SAI2_SD_B
NetC18_1: C18.1 U7.B7(IN1RN)
NetC18_2: C18.2 CN4.4
NetC19_2: C19.2 U7.C9(VMIDC)
NetC21_1: C21.1 U7.D9(AVDD1)
NetC24_1: C24.1 U7.E6(VREFC)
NetC25_1: C25.1 U7.H8(CPCB)
NetC25_2: C25.2 U7.G8(CPCA)
NetC26_1: C26.1 U7.G7(CPVOUTP)
NetC27_1: C27.1 U7.D7(IN1LN)
NetC27_2: C27.2 CN4.6
NetC28_1: C28.1 U7.H7(CPVOUTN)
NetC30_1: C30.1 CN5.6 U7.H6(HPOUT1L)
NetC30_2: C30.2 R31.1
NetC32_1: C32.1 CN5.4 U7.G6(HPOUT1R)
NetC32_2: C32.2 R33.1
NetC43_2: C43.2 U7.F1(DCVDD)
NetCN7_1: CN7.1(COMMON) U7.C3(SPKOUTRN)
NetCN7_2: CN7.2(NO) U7.B3(SPKOUTRP)
NetCN10_1: CN10.1(COMMON) U7.B1(SPKOUTLN)
NetCN10_2: CN10.2(NO) U7.A2(SPKOUTLP)
NetR35_2: R35.2 U7.F3(SDA)
NetR39_2: R39.2 U7.H1(SCLK)
NetR41_2: R41.2 U7.G2(~{CS}/ADDR)
NetR46_1: R46.1 U7.D4(LDO1ENA) U7.D5(LDO2ENA)
NetR85_1: R85.1 U16.2(LR)
NetR86_1: R86.1 U17.2(LR)

Not connected (* = marked no-connect by the designer): U7 A6(LINEOUTFB)* A8(IN2RP/VRXP)* B4(LINEOUT2P)* B5(LINEOUT1P)* B8(IN2LP/VRXN)* C4(LINEOUT2N)* C5(LINEOUT1N)* C7(IN1RP)* C8(IN1LP)* E1(GPIO2/MCLK2)* E5(GPIO7/ADCDAT2)* F4(GPIO4/LRCLK2)* F5(GPIO9/ADCDAT3)* F6(GPIO11/BCLK3)* F8(HPOUT2P)* F9(HPOUT2N)* G4(GPIO6/ADCLRCLK2)* H2(GPIO3/BCLK2)* H3(GPIO5/DACDAT2)* H4(GPIO8/DACDAT3)* H5(GPIO10/LRCLK3)*

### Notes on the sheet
- WM8994 I2C Address : 0011 0100
- Top Right
- PG15
- (near CN5) Jack Line output Green
- (near U19) Bottom Right
- Right
- Left
- Top Left
- (near CN4) Jack Line input blue
- (near U18) Bottom Left
- SPK Left
- SPK Right
- U10
- A
- B
- U8
- A = B = 21mm
- U11
- U9

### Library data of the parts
C18 C24 C27 C35 C43 = Cap_1uF_X5R_10%_0603: as C3 on sheet ST_LINK_V2-1
C19-C22 C29 C31 = Cap_4.7uF_X5R_10%_0603: Capacitor,4.7uF,16V, X5R,10%,0603,YAGEO; Manuf_Part_1: CC0603KRX5R7BB475; Order: CC0603KRX5R7BB105; Ordered by: Subcon; Fitted: YES
C23 C30 C32 C33 C41 C42 C79 C80 C84 C85 = Cap_100nF_X7R_10%_0402: as C1 on sheet ST_LINK_V2-1
C25 C26 C28 = Cap_2.2uF_X5R_10%_0603: Capacitor,2.2uF,10V, X5R,10%,0603,YAGEO; Manuf_Part_1: CC0603KRX5R6BB225; Manuf_Part_2: C0603C225K8PACTU; Manuf_2: KEMET; Ordered by: Subcon; Fitted: YES
CN4 = PJ3028B-3_BE_3PINS: Connector Jack Stereo 3.5mm, female SMT, Blue (Line input); Manuf_Part_2: PJ30280-3_BE; Ordered by: Subcon; Fitted: YES
CN5 = PJ3028B-3_GR_3PINS: Connector Jack Stereo 3.5mm, female SMT, Green (Line output); Manuf_Part_2: PJ30280-3_GR; Ordered by: Subcon; Fitted: YES
CN7 CN10 = JP2: Ordered by: Subcon
R31 R33 = Res_20_1%_0402: Resistor,20,0402,1%,YAGEO; Manuf_Part_1: RC0402FR-0720RL; Ordered by: Subcon; Fitted: YES
R35 R39 = Res_0_5%_0402: Resistor,0,0402,5%,YAGEO; Manuf_Part_1: RC0402JR-070RL; Order: 2363467; Ordered by: Subcon; Fitted: YES
R41 = Res_10K_1%_0402: as R19 on sheet ST_LINK_V2-1
R46 R85 R86 = Res_10K_1%_0402: as R11 on sheet ST_LINK_V2-1
SB1 = SB_ON: Fitted: YES; Ordered by: Subcon
SB5 = SB_OFF: Fitted: NO; Ordered by: Subcon
TP1 TP2 = TP: Test Point; Fitted: NO; Ordered by: Subcon
U7 = WM8994ECS/R: Multi-Channel Audio Hub CODEC for Smartphones; Manuf_1: Cirrus Logic; Ordered by: Subcon; Fitted: YES
U16-U19 = MP34DT01: MEMS audio sensor, omnidirectional digital microphone; Manuf_1: STM; Manuf_Part_1: MP34DT01TR-M; Provided: ST; Ref St: 9188008; ECCN_US/EU: EAR99/NEC; Fitted: YES

## Sheet Peripherals.SchDoc: Wifi, LEDs and Push Button
size A4; Author: N.P; CompanyName: STMicroelectronics; Organization: MCD/APPLIS/LMS; DocumentNumber: MB1260; Revision: D-01; SheetNumber: 11; SheetTotal: 12; Project: STM32F723e-DISCO; BOM Version: D-01
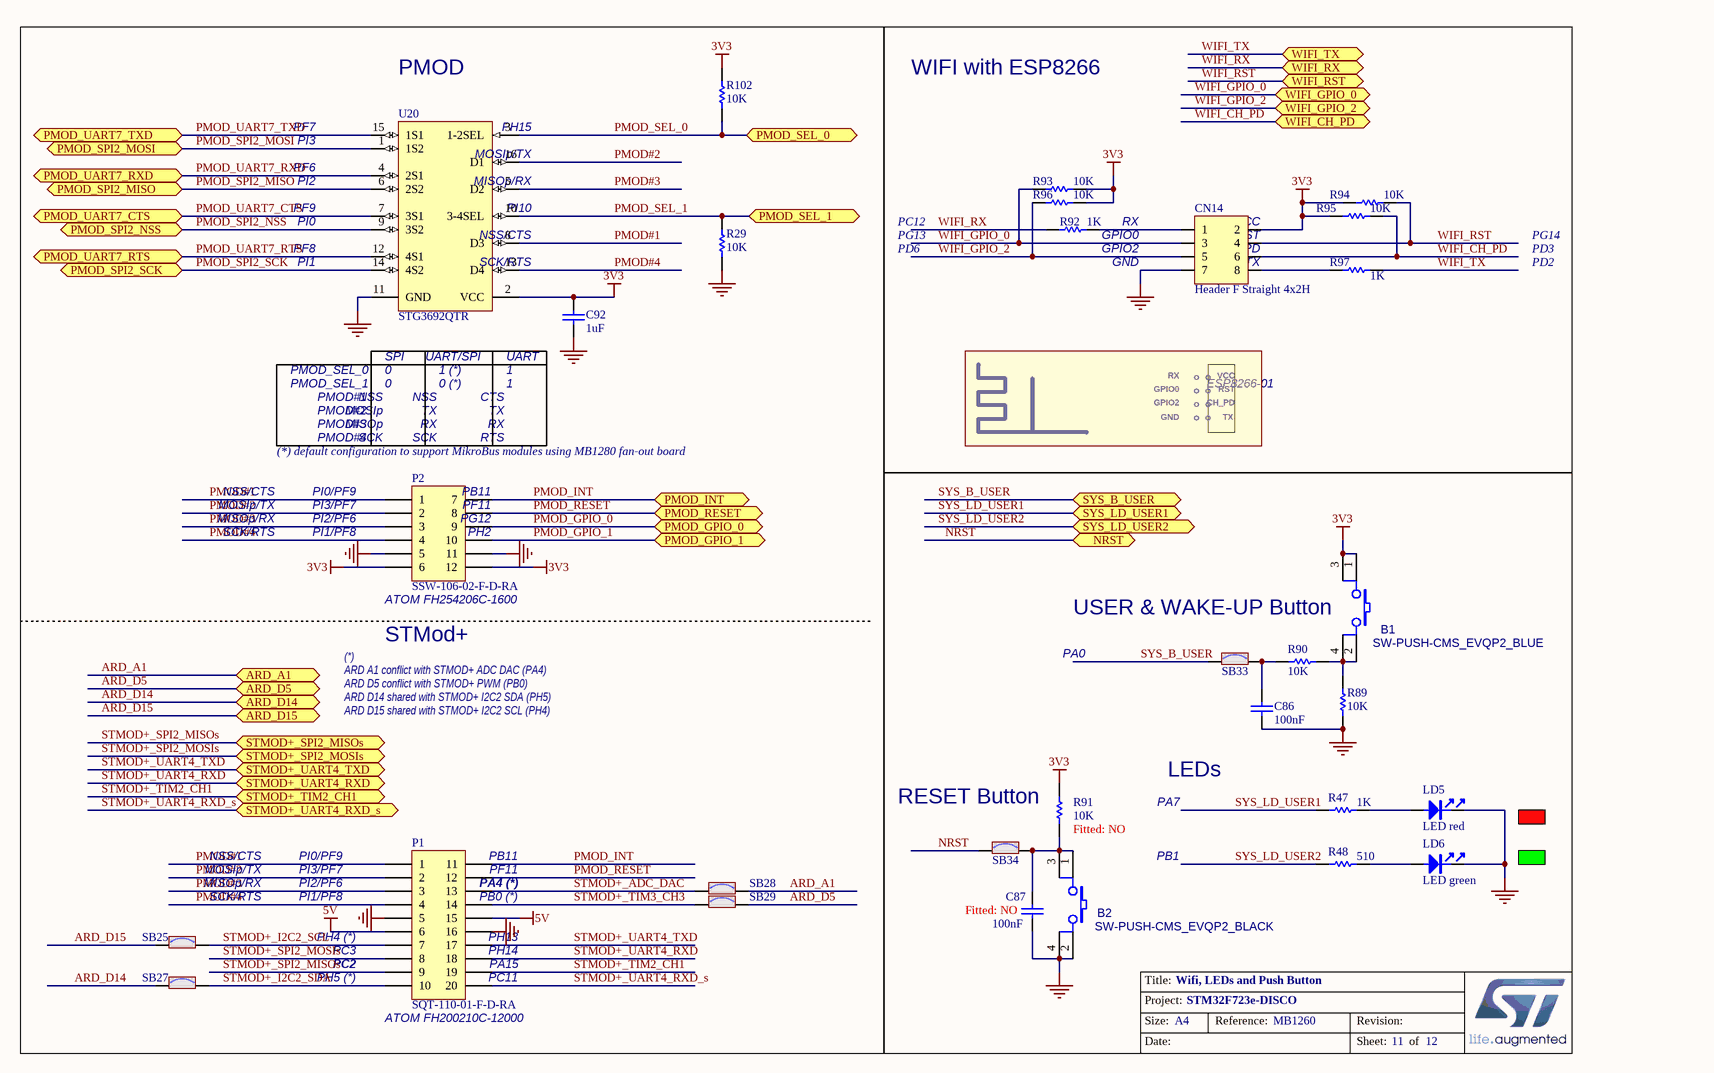
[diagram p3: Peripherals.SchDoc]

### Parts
B1  SW-PUSH-CMS_EVQP2_BLUE  [TACT_4SM_3R5X5R5]
B2  SW-PUSH-CMS_EVQP2_BLACK  [TACT_4SM_3R5X5R5]
C86  100nF  [0402C]
C87  100nF  Fitted: NO  [0402C]
C92  1uF  [0603C]
CN14  Header F Straight 4x2H  [HDR_2X4_2R54]
LD5  LED red  [0603D]
LD6  LED green  [0603D]
P1  SQT-110-01-F-D-RA  [SQT-110-01-F-D-RA]
P2  SSW-106-02-F-D-RA  [SSW-106-02-F-D-RA]
R29  10K  [0402R]
R47  value 1K  [0603R]  (hidden comment: 1K_1%_0603)
R48  value 510  [0603R]  (hidden comment: 510_1%_0603)
R89  10K  [0402R]
R90  10K  [0402R]
R91  Fitted: NO  [0402R]  (hidden comment: 10K)
R92  1K  [0402R]
R93  10K  [0402R]
R94  10K  [0402R]
R95  10K  [0402R]
R96  10K  [0402R]
R97  1K  [0402R]
R102  10K  [0402R]
SB25  Solder Bridge ON  [JP2_SMD]  (value not drawn)
SB27  Solder Bridge ON  [JP2_SMD]  (value not drawn)
SB28  Solder Bridge ON  [JP2_SMD]  (value not drawn)
SB29  Solder Bridge ON  [JP2_SMD]  (value not drawn)
SB33  Solder Bridge ON  [JP2_SMD]  (value not drawn)
SB34  Solder Bridge ON  [JP2_SMD]  (value not drawn)
U20  STG3692QTR  [QFN16_0R4_2R5X1R7]

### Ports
ARD_A1, ARD_D5, ARD_D14, ARD_D15, NRST, PMOD_GPIO_0, PMOD_GPIO_1, PMOD_INT, PMOD_RESET, PMOD_SEL_0, PMOD_SEL_1, PMOD_SPI2_MISO, PMOD_SPI2_MOSI, PMOD_SPI2_NSS, PMOD_SPI2_SCK, PMOD_UART7_CTS, PMOD_UART7_RTS, PMOD_UART7_RXD, PMOD_UART7_TXD, STMOD+_SPI2_MISOs, STMOD+_SPI2_MOSIs, STMOD+_TIM2_CH1, STMOD+_UART4_RXD, STMOD+_UART4_RXD_s, STMOD+_UART4_TXD, SYS_B_USER, SYS_LD_USER1, SYS_LD_USER2, WIFI_CH_PD, WIFI_GPIO_0, WIFI_GPIO_2, WIFI_RST, WIFI_RX, WIFI_TX

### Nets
3V3: B1.1 B1.3 C92.1 CN14.2 P2.6 P2.12 R91.2 R93.1 R94.1 R95.1 R96.1 R102.2 U20.2(VCC)
5V: P1.6 P1.15
GND: B2.2 B2.4 C86.1 C87.1 C92.2 CN14.7 LD5.2 LD6.2 P1.5 P1.16 P2.5 P2.11 R29.1 R89.1 U20.11(GND)
ARD_A1: SB28.2 ; port ARD_A1
ARD_D5: SB29.2 ; port ARD_D5
ARD_D14: SB27.1 ; port ARD_D14
ARD_D15: SB25.1 ; port ARD_D15
NRST: SB34.1 ; port NRST
PMOD#1: P1.1 P2.1 U20.8(D3)
PMOD#2: P1.2 P2.2 U20.16(D1)
PMOD#3: P1.3 P2.3 U20.5(D2)
PMOD#4: P1.4 P2.4 U20.13(D4)
PMOD_GPIO_0: P2.9 ; port PMOD_GPIO_0
PMOD_GPIO_1: P2.10 ; port PMOD_GPIO_1
PMOD_INT: P1.11 P2.7 ; port PMOD_INT
PMOD_RESET: P1.12 P2.8 ; port PMOD_RESET
PMOD_SEL_0: R102.1 U20.3(1-2SEL) ; port PMOD_SEL_0
PMOD_SEL_1: R29.2 U20.10(3-4SEL) ; port PMOD_SEL_1
PMOD_SPI2_MISO: U20.6(2S2) ; port PMOD_SPI2_MISO
PMOD_SPI2_MOSI: U20.1(1S2) ; port PMOD_SPI2_MOSI
PMOD_SPI2_NSS: U20.9(3S2) ; port PMOD_SPI2_NSS
PMOD_SPI2_SCK: U20.14(4S2) ; port PMOD_SPI2_SCK
PMOD_UART7_CTS: U20.7(3S1) ; port PMOD_UART7_CTS
PMOD_UART7_RTS: U20.12(4S1) ; port PMOD_UART7_RTS
PMOD_UART7_RXD: U20.4(2S1) ; port PMOD_UART7_RXD
PMOD_UART7_TXD: U20.15(1S1) ; port PMOD_UART7_TXD
STMOD+_ADC_DAC: P1.13 SB28.1
STMOD+_I2C2_SCL: P1.7 SB25.2
STMOD+_I2C2_SDA: P1.10 SB27.2
STMOD+_SPI2_MISOs: P1.9 ; port STMOD+_SPI2_MISOs
STMOD+_SPI2_MOSIs: P1.8 ; port STMOD+_SPI2_MOSIs
STMOD+_TIM2_CH1: P1.19 ; port STMOD+_TIM2_CH1
STMOD+_TIM3_CH3: P1.14 SB29.1
STMOD+_UART4_RXD: P1.18 ; port STMOD+_UART4_RXD
STMOD+_UART4_RXD_s: P1.20 ; port STMOD+_UART4_RXD_s
STMOD+_UART4_TXD: P1.17 ; port STMOD+_UART4_TXD
SYS_B_USER: SB33.1 ; port SYS_B_USER
SYS_LD_USER1: R47.1 ; port SYS_LD_USER1
SYS_LD_USER2: R48.1 ; port SYS_LD_USER2
WIFI_CH_PD: CN14.6 R95.2 ; port WIFI_CH_PD
WIFI_GPIO_0: CN14.3 R93.2 ; port WIFI_GPIO_0
WIFI_GPIO_2: CN14.5 R96.2 ; port WIFI_GPIO_2
WIFI_RST: CN14.4 R94.2 ; port WIFI_RST
WIFI_RX: R92.1 ; port WIFI_RX
WIFI_TX: R97.2 ; port WIFI_TX
NetB1_2: B1.2 B1.4 R89.2 R90.2
NetB2_1: B2.1 B2.3 C87.2 R91.1 SB34.2
NetC86_2: C86.2 R90.1 SB33.2
NetCN14_1: CN14.1 R92.2
NetCN14_8: CN14.8 R97.1
NetLD5_1: LD5.1 R47.2
NetLD6_1: LD6.1 R48.2

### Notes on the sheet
- PF7
- PMOD
- (near U20) PH15
- WIFI with ESP8266
- PI3
- PF6
- PI2
- (near U20) MOSIp/TX
- (near U20) MISOp/RX
- PF9
- PI1
- PI0
- PF8
- (near U20) PI10
- (near U20) NSS/CTS
- SCK/RTS
- PC12
- PG13
- PD6
- (near CN14) GND
- (near CN14) GPIO2
- (near CN14) GPIO0
- RX
- (near CN14) VCC
- (near CN14) CH_PD
- (near CN14) RST
- (near CN14) TX
- PG14
- PD3
- PD2
- PMOD_SEL_0
- PMOD_SEL_1
- PMOD#1
- 0
- NSS
- SPI
- UART/SPI
- 0 (*)
- 1 (*)
- CTS
- UART
- 1
- GPIO2
- GPIO0
- ° °
- VCC
- CH_PD
- RST
- ESP8266-01
- (near P2) (*) default configuration to support MikroBus modules using MB1280 fan-out board
- PMOD#2
- PMOD#3
- PMOD#4
- MOSIp
- MISOp
- SCK
- TX
- RTS
- GND
- NSS/CTS
- MOSIp/TX
- MISOp/RX
- (near P2) PI0/PF9
- (near P2) PI3/PF7
- (near P2) PI2/PF6
- (near P2) PI1/PF8
- (near P2) PB11
- (near P2) PF11
- (near P2) PG12
- (near P2) PH2
- (near P2) ATOM FH254206C-1600
- STMod+
- USER & WAKE-UP Button
- PA0
- (*)
  ARD A1 conflict with STMOD+ ADC DAC (PA4)
  ARD D5 conflict with STMOD+ PWM (PB0)
  ARD D14 shared with STMOD+ I2C2 SDA (PH5)
  ARD D15 shared with STMOD+ I2C2 SCL (PH4)
- RESET Button
- LEDs
- PA7
- (near P1) PI0/PF9
- (near P1) PI3/PF7
- PB11
- PF11
- PB1
- (near P1) PI2/PF6
- (near P1) PI1/PF8
- (near P1) PH4 (*)
- PA4 (*)
- PB0 (*)
- PH13
- (near P1) PC3
- (near P1) PC2
- (near P1) PH5 (*)
- PH14
- PA15
- PC11
- (near P1) ATOM FH200210C-12000

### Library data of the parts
B1 = SW-PUSH-CMS_EVQP2_BLUE: EVQP2 - 4.7mm x 3.5 mm SMD Light Touch Switch; Manuf_2: Panasonic; Manuf_Part_2: EVQP2B02B; Manuf_Part_1: C-TS-02H-2.5-B-V-T/R; Manuf_1: Jiubaba; Ordered by: Subcon; Fitted: YES
B2 = SW-PUSH-CMS_EVQP2_BLACK: EVQP2 - 4.7mm x 3.5 mm SMD Light Touch Switch; Manuf_2: Panasonic; Manuf_Part_2: EVQP2F02K; Manuf_1: Jiubaba; Manuf_Part_1: C-TS-02H-2.5-K-V-T/R; Ordered by: Subcon; Fitted: YES
C86 = Cap_100nF_X7R_10%_0402: as C1 on sheet ST_LINK_V2-1
C87 = Cap_100nF_X7R_10%_0402: Capacitor,100nF,16V,X7R,10%,0402,YAGEO; Manuf_Part_1: CC0402KRX7R7BB104; Ordered by: Subcon
C92 = Cap_1uF_X5R_10%_0603: as C3 on sheet ST_LINK_V2-1
CN14 = Header 4X2F: Header Female, 4-Pin, Dual row, Straight; Manuf_Part_1: BL 2-8G; Manuf_1: Fischer Electronik; Fitted: YES; Ordered by: Subcon
LD5 = LED_red: as LD2 on sheet ST_LINK_V2-1
LD6 = LED_green: LED green 0603; Manuf_1: everlight; Manuf_Part_1: 19-213SYGC/S530-E2/TR8; Ordered by: Subcon; Fitted: YES
P1 = Header 10X2 TH RA 2mm: 20 Position Receptacle Connector 0.079" (2.00mm) Through Hole Right Angle; Manuf_1: Samtec; Manuf_2: ATOM; Manuf_Part_2: FH200210C-12000; Ordered by: Subcon; Fitted: YES
P2 = Header 6X2 TH RA 2.54mm: 12 Position Receptacle Connector 0.100" (2.54mm) Through Hole Right Angle; Manuf_1: Samtec; Manuf_2: ATOM; Manuf_Part_2: FH254206C-1600; Ordered by: Subcon; Fitted: YES
R29 R89 R90 R93-R96 R102 = Res_10K_1%_0402: as R11 on sheet ST_LINK_V2-1
R47 = Res_1K_1%_0603: Resistor,1K,0603,1%,YAGEO; Manuf_Part_1: RC0603FR-071KL; Ordered by: Subcon; Fitted: YES
R48 = Res_510_1%_0603: Resistor,510,0603,1%,YAGEO; Manuf_Part_1: RC0603FR-07510RL; Manuf_Part_2: RT0603FRE07510RL; Ordered by: Subcon; Fitted: YES
R91 = Res_10K_1%_0402: as R19 on sheet ST_LINK_V2-1
R92 R97 = Res_1K_1%_0402: as R1 on sheet ST_LINK_V2-1
SB25 SB27-SB29 SB33 SB34 = SB_ON: Fitted: YES; Ordered by: Subcon
U20 = STG3692QTR: Low voltage high bandwidth quad SPDT switch; Manuf_1: STM; Fitted: YES; ECCN_US/EU: EAR99/NEC; Ordered by: ST

## Sheet ARDUINO.SchDoc: Arduino UNO connectors
size A4; Author: N.P; CompanyName: STMicroelectronics; Organization: MCD/APPLIS/LMS; DocumentNumber: MB1260; Revision: D-01; SheetNumber: 7; SheetTotal: 12; Project: STM32F723e-DISCO; BOM Version: D-01
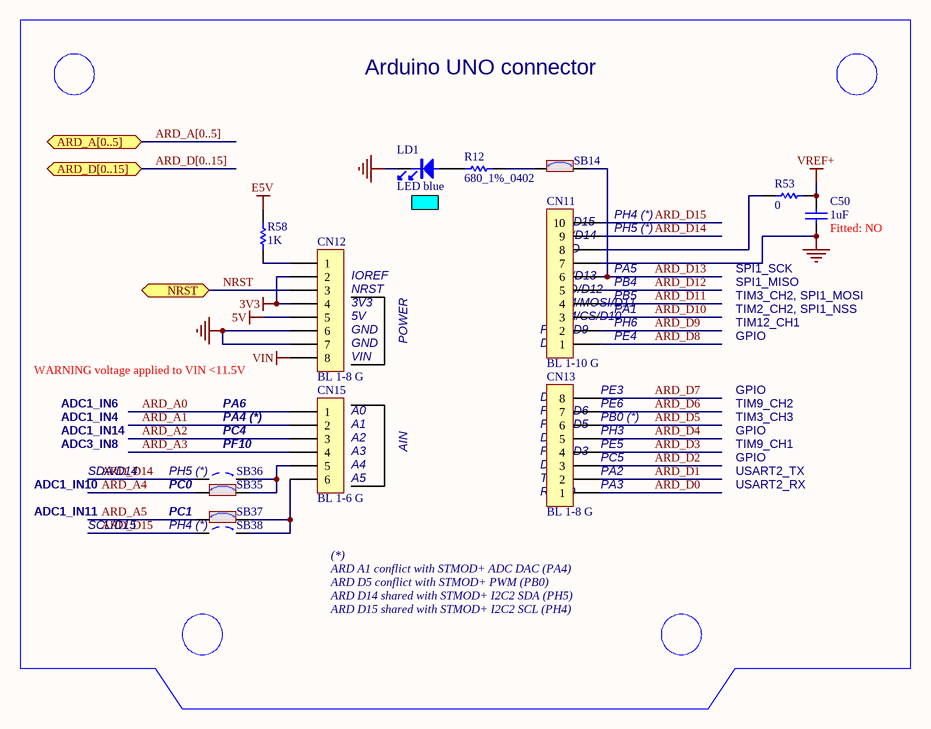
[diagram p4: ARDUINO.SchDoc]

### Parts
C50  1uF  Fitted: NO  [0603C]
CN11  BL 1-10 G  [HDR_1X10_2R54_W]
CN12  BL 1-8 G  [HDR_1X8_2R54_W]
CN13  BL 1-8 G  [HDR_1X8_2R54_W]
CN15  BL 1-6 G  [HDR_1X6_2R54_W]
LD1  LED blue  [0603D]
R12  680_1%_0402  [0402R]
R53  0  [0402R]
R58  1K  [0402R]
SB14  Solder Bridge ON  [JP2_SMD]  (value not drawn)
SB35  Solder Bridge ON  [JP2_SMD]  (value not drawn)
SB36  Solder Bridge OFF  [JP2_SMD]  (value not drawn)
SB37  Solder Bridge ON  [JP2_SMD]  (value not drawn)
SB38  Solder Bridge OFF  [JP2_SMD]  (value not drawn)

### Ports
ARD_A[0..5], ARD_D[0..15], NRST

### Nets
3V3: CN12.2 CN12.4
5V: CN12.5
E5V: R58.2
GND: C50.1 CN11.7 CN12.6 CN12.7 LD1.2
VIN: CN12.8
VREF+: C50.2 R53.2
ARD_A0: CN15.1
ARD_A1: CN15.2
ARD_A2: CN15.3
ARD_A3: CN15.4
ARD_A4: SB35.1
ARD_A5: SB37.1
ARD_D0: CN13.1
ARD_D1: CN13.2
ARD_D2: CN13.3
ARD_D3: CN13.4
ARD_D4: CN13.5
ARD_D5: CN13.6
ARD_D6: CN13.7
ARD_D7: CN13.8
ARD_D8: CN11.1
ARD_D9: CN11.2
ARD_D10: CN11.3
ARD_D11: CN11.4
ARD_D12: CN11.5
ARD_D13: CN11.6 SB14.2
ARD_D14: CN11.9 SB36.1
ARD_D15: CN11.10 SB38.1
NRST: CN12.3 ; port NRST
NetCN11_8: CN11.8 R53.1
NetCN12_1: CN12.1 R58.1
NetCN15_5: CN15.5 SB35.2 SB36.2
NetCN15_6: CN15.6 SB37.2 SB38.2
NetLD1_1: LD1.1 R12.1
NetR12_2: R12.2 SB14.1

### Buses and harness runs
bus ARD_A[0..5] = port ARD_A[0..5]
bus ARD_D[0..15] = port ARD_D[0..15]

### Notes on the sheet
- Arduino UNO connector
- PH4 (*)
- (near CN12) IOREF
- (near CN12) NRST
- (near CN11) SDA/D14
- (near CN11) SCL/D15
- (near CN11) SCK/D13
- (near CN11) MISO/D12
- (near CN11) AVDD
- (near CN11) GND
- (near CN11) PB4
- (near CN11) PA5
- (near CN11) PH5 (*)
- SPI1_MISO
- SPI1_SCK
- (near CN12) 3V3
- (near CN12) 5V
- (near CN12) GND
- POWER
- (near CN11) D8
- (near CN11) PWM/D9
- (near CN11) PWM/CS/D10
- (near CN11) PWM/MOSI/D11
- (near CN11) PA1
- (near CN11) PE4
- (near CN11) PH6
- (near CN11) PB5
- TIM12_CH1
- TIM2_CH2, SPI1_NSS
- TIM3_CH2, SPI1_MOSI
- GPIO
- WARNING voltage applied to VIN <11.5V
- ADC1_IN4
- ADC1_IN6
- PA6
- PA4 (*)
- (near CN15) A0
- (near CN15) A1
- (near CN12) VIN
- (near CN13) PWM/D5
- (near CN13) PWM/D6
- (near CN13) D7
- (near CN13) PE6
- (near CN13) PE3
- (near CN13) PB0 (*)
- TIM3_CH3
- TIM9_CH2
- ADC1_IN10
- ADC3_IN8
- ADC1_IN14
- SDA/D14
- (near SB36) PH5 (*)
- PC0
- PC4
- PF10
- (near CN15) A2
- (near CN15) A3
- (near CN15) A4
- (near CN15) A5
- AIN
- (near CN13) TX/D1
- (near CN13) D2
- (near CN13) D4
- (near CN13) PWM/D3
- (near CN13) PA2
- (near CN13) PC5
- (near CN13) PE5
- (near CN13) PH3
- (near CN13) PA3
- USART2_RX
- USART2_TX
- TIM9_CH1
- ADC1_IN11
- SCL/D15
- PC1
- (near CN13) RX/D0
- (*)
  ARD A1 conflict with STMOD+ ADC DAC (PA4)
  ARD D5 conflict with STMOD+ PWM (PB0)
  ARD D14 shared with STMOD+ I2C2 SDA (PH5)
  ARD D15 shared with STMOD+ I2C2 SCL (PH4)

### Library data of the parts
C50 = Cap_1uF_X5R_10%_0603: Capacitor,1uF,16V,X5R,10%,0603,YAGEO; Manuf_Part_1: CC0603KRX5R7BB105; Ordered by: Subcon
CN11 = Header 10X1_Female_THT: Header, 10-Pin, Single row, female, THT, 2.54; Manuf_1: Fischer Electronik; Ordered by: Subcon; Fitted: YES
CN12 CN13 = Header 8X1_Female_THT: Header, 8-Pins, Single row, female, THT, 2.54; Manuf_1: Fischer Electronik; Ordered by: Subcon; Fitted: YES
CN15 = Header 6X1_Female_THT: Header, 6-Pins, Single row, female THT, 2.54; Manuf_1: Fischer Electronik; Ordered by: Subcon; Fitted: YES
LD1 = LED_blue: LED blue 0603; Manuf_1: everlight; Manuf_Part_1: 19-213SUBC/S400-A5/S208-2/S4/TR8; ECCN_US/EU: EAR99/NEC; Fitted: YES; Ordered by: Subcon
R12 = Res_680_1%_0402: Resistor,680,0402,1%,YAGEO; Manuf_Part_1: RC0402FR-07680RL; Manuf_Part_2: RT0402FRE07680RL; Ordered by: Subcon; Fitted: YES; Value: 680
R53 = Res_0_5%_0402: as R35 on sheet AUDIO
R58 = Res_1K_1%_0402: as R1 on sheet ST_LINK_V2-1
SB14 SB35 SB37 = SB_ON: Fitted: YES; Ordered by: Subcon
SB36 SB38 = SB_OFF: Fitted: NO; Ordered by: Subcon

## Sheet PSRAM.SchDoc: PSRAM
size A4; Author: N.P; CompanyName: STMicroelectronics; Organization: MCD/APPLIS/LMS; DocumentNumber: MB1260; Revision: D-01; SheetNumber: 5; SheetTotal: 12; Project: STM32F723e-DISCO; BOM Version: D-01
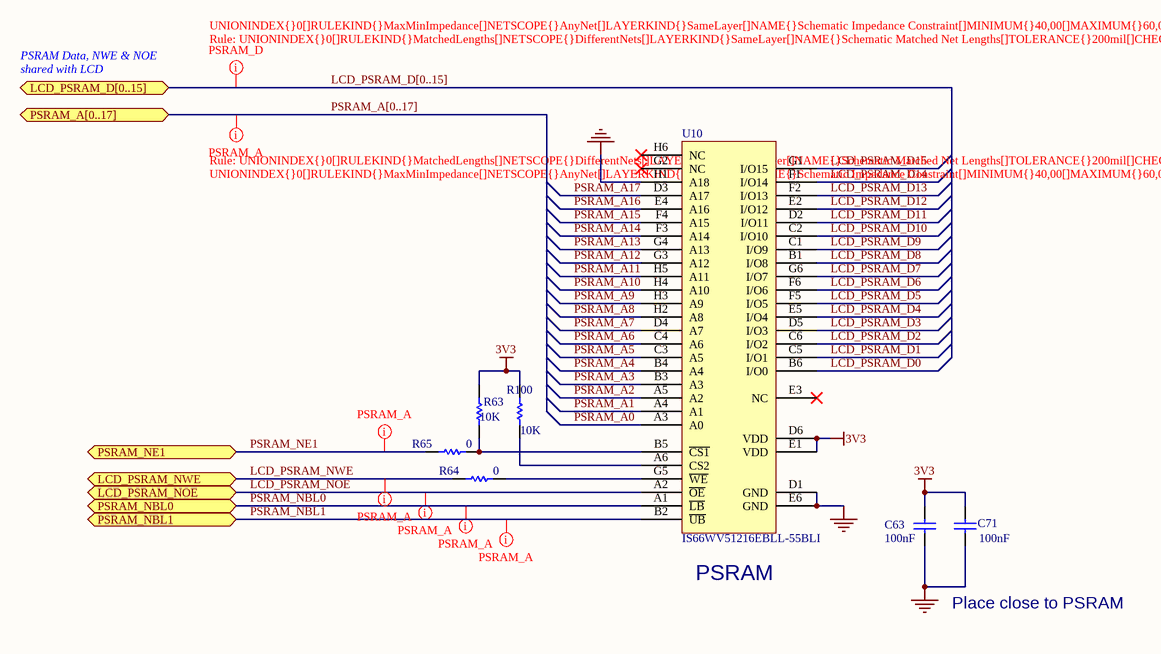
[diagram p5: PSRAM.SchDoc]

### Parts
C63  100nF  [0402C]
C71  100nF  [0402C]
R63  value 10K  [0603R]  (hidden comment: 10K_1%_0603)
R64  value 0  [0603R-GS]  (hidden comment: 0_5%_0603)
R65  value 0  [0603R-GS]  (hidden comment: 0_5%_0603)
R100  value 10K  [0603R]  (hidden comment: 10K_1%_0603)
U10  IS66WV51216EBLL-55BLI  [FBGA48_0R75_6X8]

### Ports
LCD_PSRAM_D[0..15], LCD_PSRAM_NOE, LCD_PSRAM_NWE, PSRAM_A[0..17], PSRAM_NBL0, PSRAM_NBL1, PSRAM_NE1

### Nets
3V3: C63.2 C71.2 R63.2 R100.2 U10.D6(VDD) U10.E1(VDD)
GND: C63.1 C71.1 U10.D1(GND) U10.E6(GND) U10.H1(A18)
LCD_PSRAM_D0: U10.B6(I/O0)
LCD_PSRAM_D1: U10.C5(I/O1)
LCD_PSRAM_D2: U10.C6(I/O2)
LCD_PSRAM_D3: U10.D5(I/O3)
LCD_PSRAM_D4: U10.E5(I/O4)
LCD_PSRAM_D5: U10.F5(I/O5)
LCD_PSRAM_D6: U10.F6(I/O6)
LCD_PSRAM_D7: U10.G6(I/O7)
LCD_PSRAM_D8: U10.B1(I/O8)
LCD_PSRAM_D9: U10.C1(I/O9)
LCD_PSRAM_D10: U10.C2(I/O10)
LCD_PSRAM_D11: U10.D2(I/O11)
LCD_PSRAM_D12: U10.E2(I/O12)
LCD_PSRAM_D13: U10.F2(I/O13)
LCD_PSRAM_D14: U10.F1(I/O14)
LCD_PSRAM_D15: U10.G1(I/O15)
LCD_PSRAM_NOE: U10.A2(~{OE}) ; port LCD_PSRAM_NOE
LCD_PSRAM_NWE: R64.1 ; port LCD_PSRAM_NWE
PSRAM_A0: U10.A3(A0)
PSRAM_A1: U10.A4(A1)
PSRAM_A2: U10.A5(A2)
PSRAM_A3: U10.B3(A3)
PSRAM_A4: U10.B4(A4)
PSRAM_A5: U10.C3(A5)
PSRAM_A6: U10.C4(A6)
PSRAM_A7: U10.D4(A7)
PSRAM_A8: U10.H2(A8)
PSRAM_A9: U10.H3(A9)
PSRAM_A10: U10.H4(A10)
PSRAM_A11: U10.H5(A11)
PSRAM_A12: U10.G3(A12)
PSRAM_A13: U10.G4(A13)
PSRAM_A14: U10.F3(A14)
PSRAM_A15: U10.F4(A15)
PSRAM_A16: U10.E4(A16)
PSRAM_A17: U10.D3(A17)
PSRAM_NBL0: U10.A1(~{LB}) ; port PSRAM_NBL0
PSRAM_NBL1: U10.B2(~{UB}) ; port PSRAM_NBL1
PSRAM_NE1: R65.1 ; port PSRAM_NE1
NetR63_1: R63.1 R65.2 U10.B5(~{CS1})
NetR64_2: R64.2 U10.G5(~{WE})
NetR100_1: R100.1 U10.A6(CS2)

Not connected (* = marked no-connect by the designer): U10 E3(NC)* G2(NC)* H6(NC)*

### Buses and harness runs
bus LCD_PSRAM_D[0..15] = port LCD_PSRAM_D[0..15]
bus PSRAM_A[0..17] = port PSRAM_A[0..17]

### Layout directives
rule Matched Net Lengths [Tolerance = 200mil]; rule Impedance Constraint [Min = 40.00    Max = 60.00    ]: (no net found under the mark), LCD_PSRAM_NOE, LCD_PSRAM_NWE, PSRAM_NBL0, PSRAM_NBL1, PSRAM_NE1

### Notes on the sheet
- PSRAM Data, NWE & NOE shared with LCD
- (near U10) PSRAM
- Place close to PSRAM

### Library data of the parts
C63 C71 = Cap_100nF_X7R_10%_0402: as C1 on sheet ST_LINK_V2-1
R63 R100 = Res_10K_1%_0603: Resistor,10K,0603,1%,YAGEO; Manuf_Part_1: RC0603FR-0710KL; Ordered by: Subcon; Fitted: YES
R64 R65 = Res_0_5%_0603: Resistor,0,0603,5%,YAGEO; Manuf_Part_1: RC0603JR-070RL; Order: 2363481; Ordered by: Subcon; Fitted: YES
U10 = IS66WV51216EBLL-55BLI: IC SRAM 8MBIT 55NS 48MINIBGA 6mm x 8mm; Manuf_1: ISSI, Integrated Silicon Solution Inc; Fitted: YES; Ordered_By: Subcon

## Sheet USB_OTG_FS.SchDoc: USB OTG FS
size A4; Author: N.P; CompanyName: STMicroelectronics; Organization: MCD/APPLIS/LMS; DocumentNumber: MB1260; Revision: D-01; SheetNumber: 9; SheetTotal: 12; Project: STM32F723e-DISCO; BOM Version: D-01
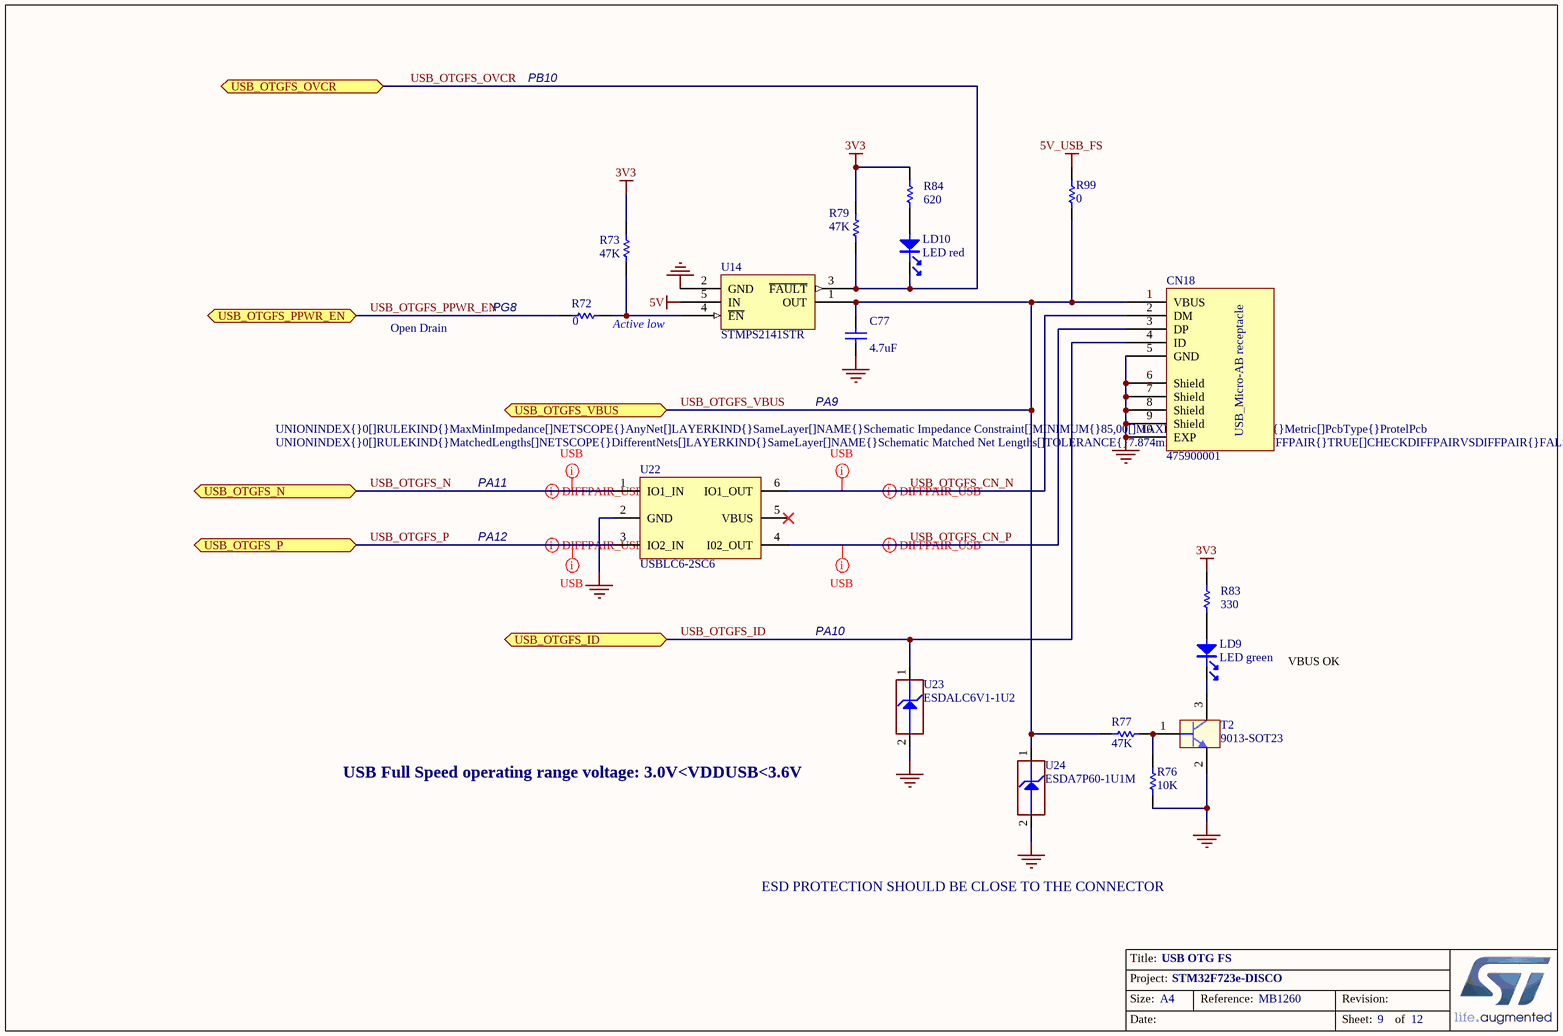
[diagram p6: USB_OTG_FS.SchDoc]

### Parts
C77  4.7uF  [0603C]
CN18  475900001  [MOLEX_47590001]
LD9  LED green  [0603D]
LD10  LED red  [0603D]
R72  value 0  [0603R-GS]  (hidden comment: 0_5%_0603)
R73  value 47K  [0402R]  (hidden comment: 47K_1%_0402)
R76  10K  [0402R]
R77  value 47K  [0402R]  (hidden comment: 47K_1%_0402)
R79  value 47K  [0402R]  (hidden comment: 47K_1%_0402)
R83  value 330  [0603R]  (hidden comment: 330_1%_0603)
R84  value 620  [0603R]  (hidden comment: 620_1%_0603)
R99  value 0  [0603R-GS]  (hidden comment: 0_5%_0603)
T2  9013-SOT23  [SOT-23]
U14  STMPS2141STR  [SOT23-5]
U22  USBLC6-2SC6  [SOT23-6]
U23  ESDALC6V1-1U2  [ESD_ST0201]
U24  ESDA7P60-1U1M  [ESD_ST0201]

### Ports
USB_OTGFS_ID, USB_OTGFS_N, USB_OTGFS_OVCR, USB_OTGFS_P, USB_OTGFS_PPWR_EN, USB_OTGFS_VBUS

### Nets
3V3: R73.2 R79.2 R83.2 R84.2
5V: U14.5(IN)
5V_USB_FS: R99.2
GND: C77.2 CN18.5(GND) CN18.6(Shield) CN18.7(Shield) CN18.8(Shield) CN18.9(Shield) CN18.10(EXP) R76.1 T2.2(E) U14.2(GND) U22.2(GND) U23.2(GND) U24.2(GND)
USB_OTGFS_CN_N: CN18.2(DM) U22.6(IO1_OUT)
USB_OTGFS_CN_P: CN18.3(DP) U22.4(I02_OUT)
USB_OTGFS_ID: CN18.4(ID) U23.1(IO1) ; port USB_OTGFS_ID
USB_OTGFS_N: U22.1(IO1_IN) ; port USB_OTGFS_N
USB_OTGFS_OVCR: LD10.2 R79.1 U14.3(~{FAULT}) ; port USB_OTGFS_OVCR
USB_OTGFS_P: U22.3(IO2_IN) ; port USB_OTGFS_P
USB_OTGFS_PPWR_EN: R72.1 ; port USB_OTGFS_PPWR_EN
USB_OTGFS_VBUS: C77.1 CN18.1(VBUS) R77.2 R99.1 U14.1(OUT) U24.1(IO1) ; port USB_OTGFS_VBUS
NetLD9_1: LD9.1 R83.1
NetLD9_2: LD9.2 T2.3(C)
NetLD10_1: LD10.1 R84.1
NetR72_2: R72.2 R73.1 U14.4(~{EN})
NetR76_2: R76.2 R77.1 T2.1(B)

Not connected (* = marked no-connect by the designer): U22 5(VBUS)*

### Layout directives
rule Undefined; rule Matched Net Lengths [Tolerance = 0.2mm]; rule Impedance Constraint [Min = 85.00    Max = 95.00    ]: USB_OTGFS_CN_N, USB_OTGFS_CN_P, USB_OTGFS_N, USB_OTGFS_P
differential pair; rule Impedance Constraint [Min = 85.00    Max = 95.00    ]: USB_OTGFS_CN_N, USB_OTGFS_CN_P, USB_OTGFS_N, USB_OTGFS_P

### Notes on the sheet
- PB10
- (near R72) PG8
- Open Drain
- (near R72) Active low
- PA9
- PA11
- PA12
- PA10
- VBUS OK
- USB Full Speed operating range voltage: 3.0V<VDDUSB<3.6V
- ESD PROTECTION SHOULD BE CLOSE TO THE CONNECTOR

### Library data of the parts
C77 = Cap_4.7uF_X5R_10%_0603: as C19 on sheet AUDIO
CN18 = 475900001: USB-MICRO-AB, 47590-0001, SMT, MOLEX; Ordered by: Subcon; Fitted: YES
LD9 = LED_green: as LD6 on sheet Peripherals
LD10 = LED_red: as LD2 on sheet ST_LINK_V2-1
R72 R99 = Res_0_5%_0603: as R64 on sheet PSRAM
R73 R77 R79 = Res_47K_1%_0402: Resistor,47K,0402,1%,YAGEO; Manuf_Part_1: RC0402FR-0747KL; Order: 9239430; Ordered by: Subcon; Fitted: YES
R76 = Res_10K_1%_0402: as R11 on sheet ST_LINK_V2-1
R83 = Res_330_1%_0603: Resistor,330,0603,1%,YAGEO; Manuf_Part_1: RC0603FR-07330RL; Manuf_Part_2: RT0603FRE07330RL; Ordered by: Subcon; Fitted: YES
R84 = Res_620_1%_0603: Resistor,620,0603,1%,VISHAY; Manuf_Part_1: CRCW0603620RFKEA; Manuf_1: VISHAY DRALORIC; Order: 2122341; Ordered by: Subcon; Fitted: YES
T2 = 9013-SOT23: as T3 on sheet ST_LINK_V2-1
U14 = STMPS2141STR: Enhanced single channel power switches; Manuf_1: STM; Provided: ST; ECCN_US/EU: EAR99/NEC; Ref St: 9159003; Fitted: YES
U22 = USBLC6-2SC6: as U21 on sheet ST_LINK_V2-1
U23 = ESDALC6V1-1U2: Dual Transil array for ESD protection; Manuf_1: STM; Ref St: .; ECCN_US/EU: EAR99/NEC; Fitted: YES; Provided: ST
U24 = MCD-00251: High power transient voltage suppressor, 7V breakdown; Manuf_1: STM; ECCN_US/EU: EAR99/NEC; Fitted: YES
